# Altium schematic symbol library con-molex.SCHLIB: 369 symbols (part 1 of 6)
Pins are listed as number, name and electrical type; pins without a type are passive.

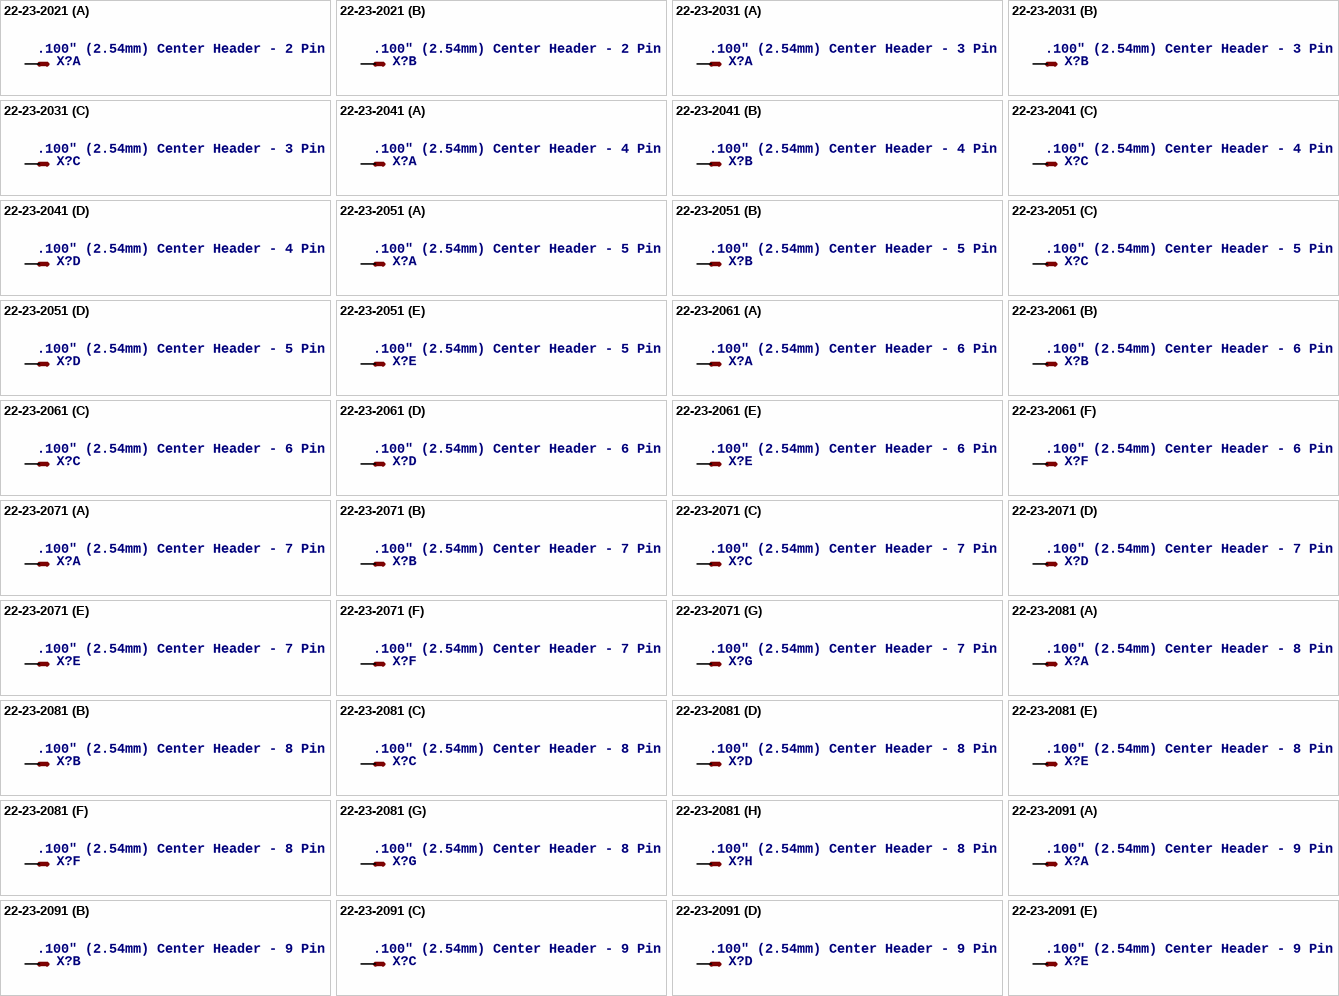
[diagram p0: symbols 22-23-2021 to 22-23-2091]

## 22-23-2021
designator X?, comment .100" (2.54mm) Center Header - 2 Pin
MF: MOLEX
footprint 22-23-2021
part A pins: 1 S
part B pins: 2 S

## 22-23-2031
designator X?, comment .100" (2.54mm) Center Header - 3 Pin
MF: MOLEX
footprint 22-23-2031
part A pins: 1 S
part B pins: 2 S
part C pins: 3 S

## 22-23-2041
designator X?, comment .100" (2.54mm) Center Header - 4 Pin
MF: MOLEX
footprint 22-23-2041
part A pins: 1 S
part B pins: 2 S
part C pins: 3 S
part D pins: 4 S

## 22-23-2051
designator X?, comment .100" (2.54mm) Center Header - 5 Pin
MF: MOLEX
footprint 22-23-2051
part A pins: 1 S
part B pins: 2 S
part C pins: 3 S
part D pins: 4 S
part E pins: 5 S

## 22-23-2061
designator X?, comment .100" (2.54mm) Center Header - 6 Pin
MF: MOLEX
footprint 22-23-2061
part A pins: 1 S
part B pins: 2 S
part C pins: 3 S
part D pins: 4 S
part E pins: 5 S
part F pins: 6 S

## 22-23-2071
designator X?, comment .100" (2.54mm) Center Header - 7 Pin
MF: MOLEX
footprint 22-23-2071
part A pins: 1 S
part B pins: 2 S
part C pins: 3 S
part D pins: 4 S
part E pins: 5 S
part F pins: 6 S
part G pins: 7 S

## 22-23-2081
designator X?, comment .100" (2.54mm) Center Header - 8 Pin
MF: MOLEX
footprint 22-23-2081
part A pins: 1 S
part B pins: 2 S
part C pins: 3 S
part D pins: 4 S
part E pins: 5 S
part F pins: 6 S
part G pins: 7 S
part H pins: 8 S

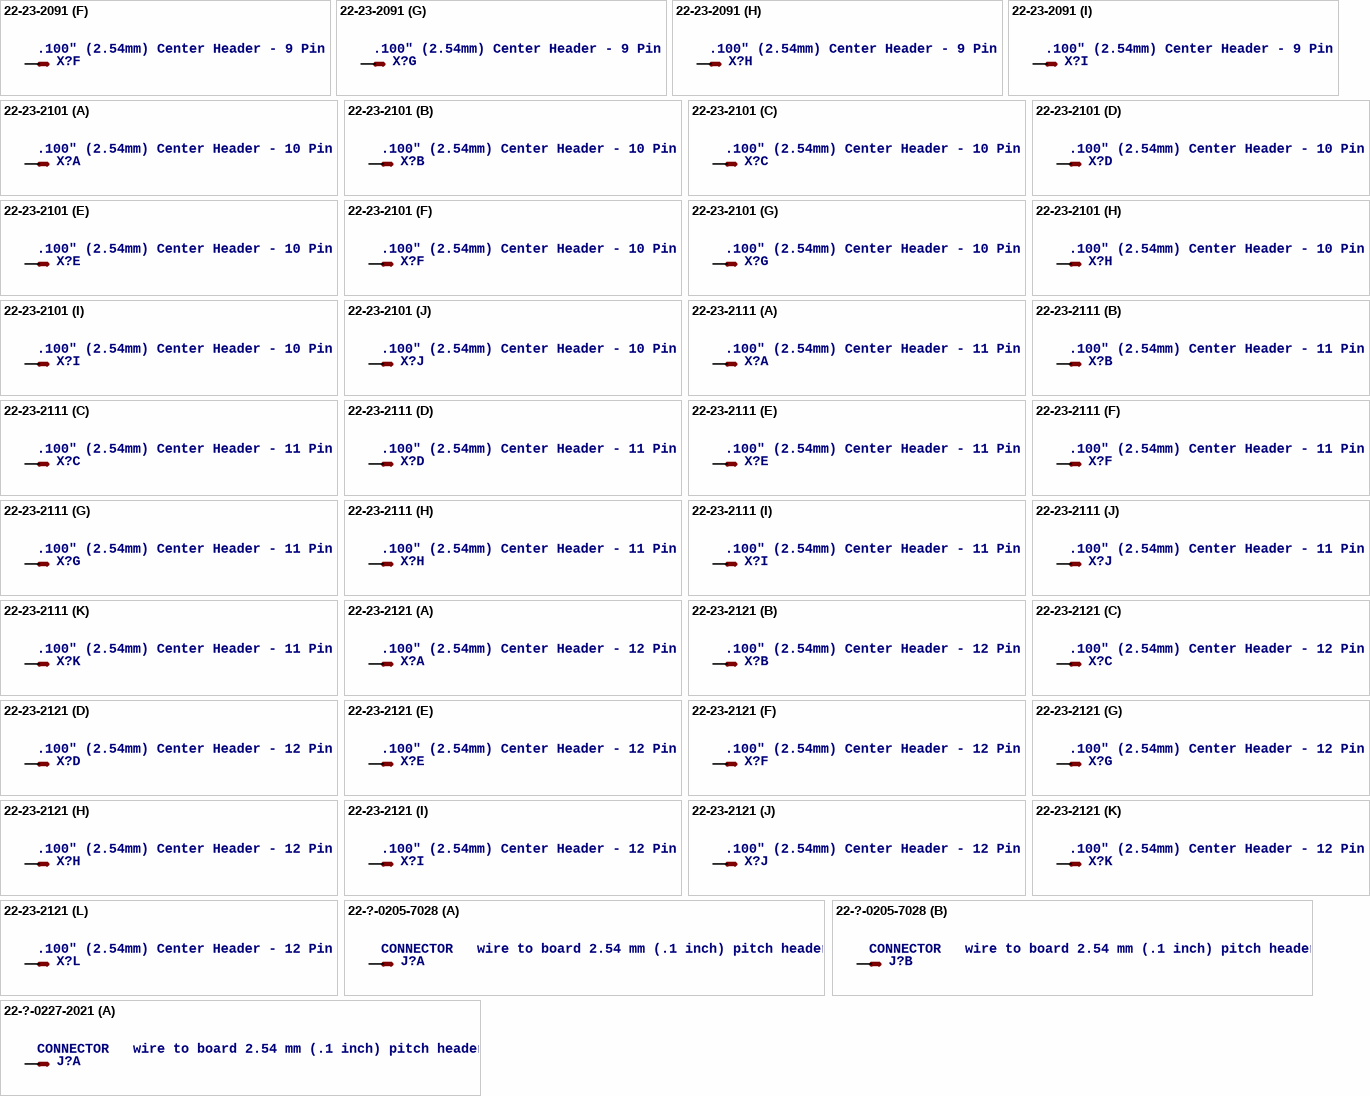
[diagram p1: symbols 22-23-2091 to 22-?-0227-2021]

## 22-23-2091
designator X?, comment .100" (2.54mm) Center Header - 9 Pin
MF: MOLEX
footprint 22-23-2091
part A pins: 1 S
part B pins: 2 S
part C pins: 3 S
part D pins: 4 S
part E pins: 5 S
part F pins: 6 S
part G pins: 7 S
part H pins: 8 S
part I pins: 9 S

## 22-23-2101
designator X?, comment .100" (2.54mm) Center Header - 10 Pin
MF: MOLEX
footprint 22-23-2101
part A pins: 1 S
part B pins: 2 S
part C pins: 3 S
part D pins: 4 S
part E pins: 5 S
part F pins: 6 S
part G pins: 7 S
part H pins: 8 S
part I pins: 9 S
part J pins: 10 S

## 22-23-2111
designator X?, comment .100" (2.54mm) Center Header - 11 Pin
MF: MOLEX
footprint 22-23-2111
part A pins: 1 S
part B pins: 2 S
part C pins: 3 S
part D pins: 4 S
part E pins: 5 S
part F pins: 6 S
part G pins: 7 S
part H pins: 8 S
part I pins: 9 S
part J pins: 10 S
part K pins: 11 S

## 22-23-2121
designator X?, comment .100" (2.54mm) Center Header - 12 Pin
MF: MOLEX
footprint 22-23-2121
part A pins: 1 S
part B pins: 2 S
part C pins: 3 S
part D pins: 4 S
part E pins: 5 S
part F pins: 6 S
part G pins: 7 S
part H pins: 8 S
part I pins: 9 S
part J pins: 10 S
part K pins: 11 S
part L pins: 12 S

## 22-?-0205-7028
designator J?, comment CONNECTOR   wire to board 2.54 mm (.1 inch) pitch header
footprint 7395-02
part A pins: 1 S
part B pins: 2 S

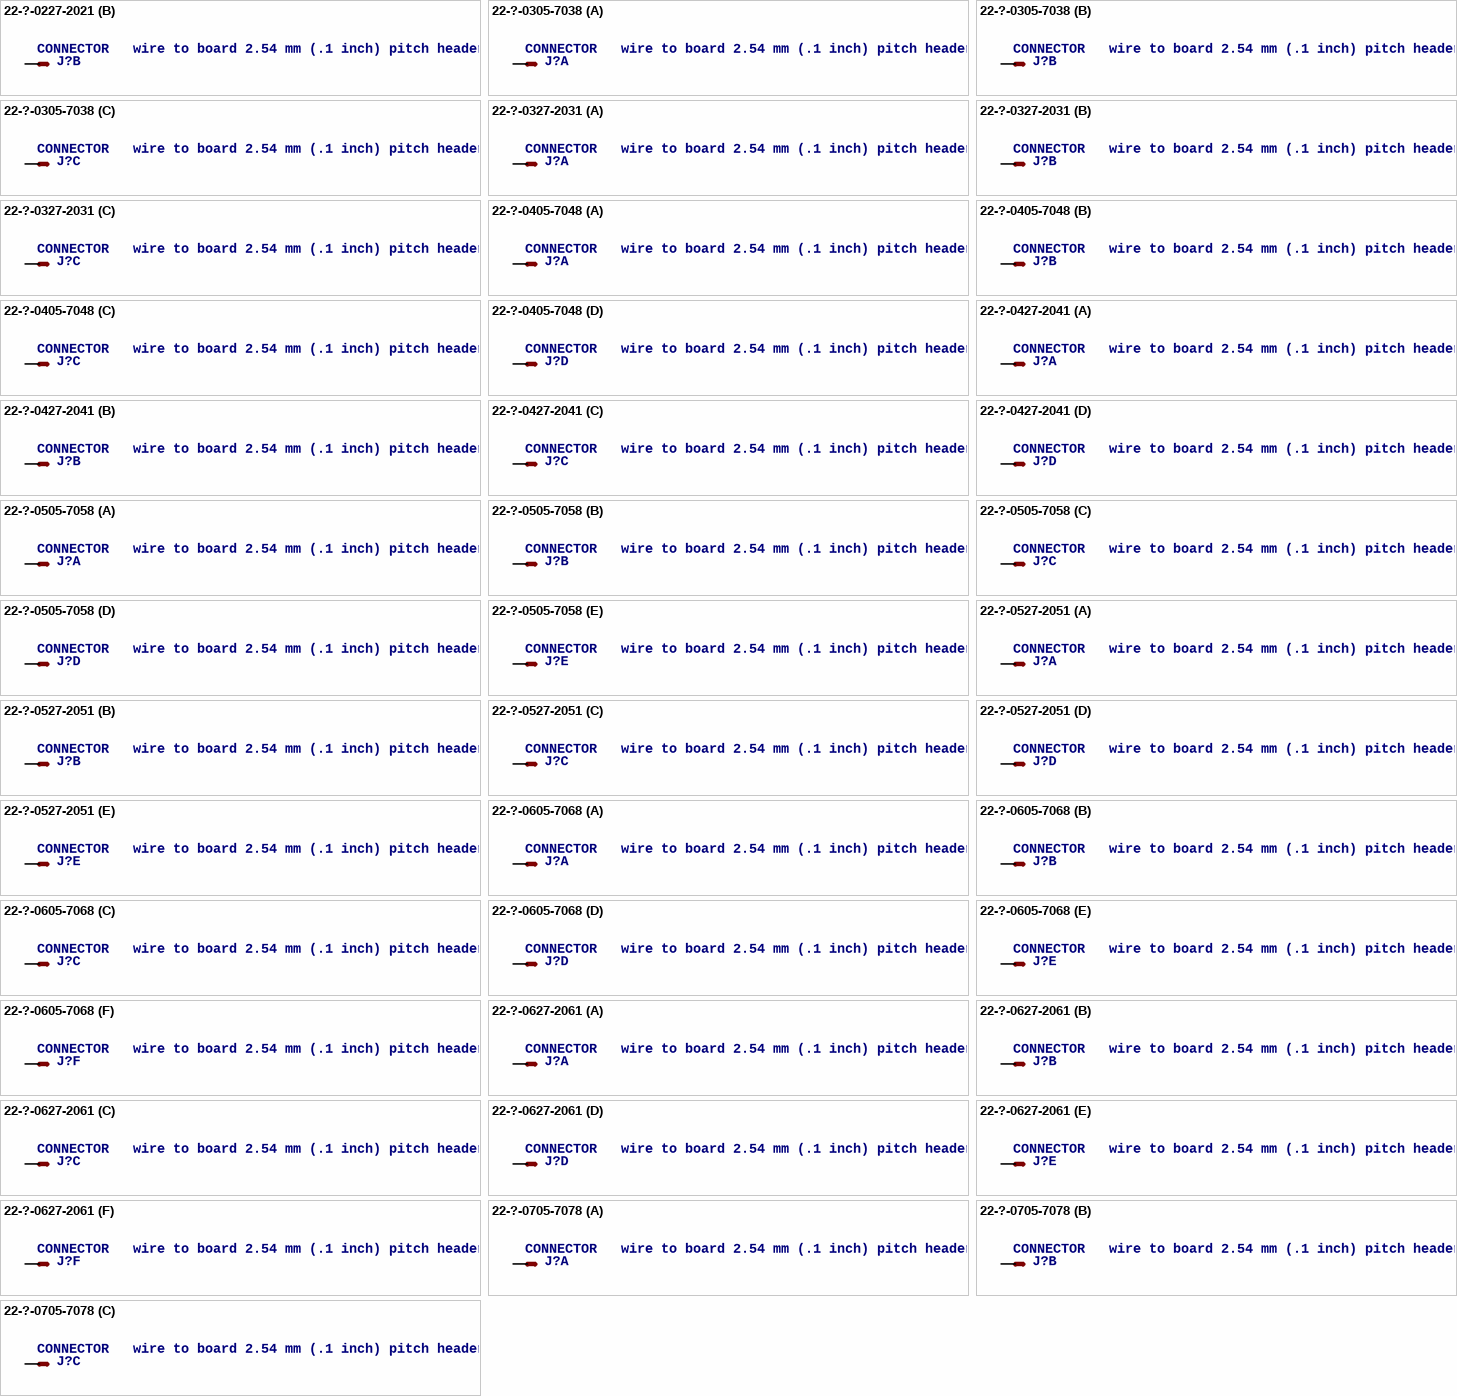
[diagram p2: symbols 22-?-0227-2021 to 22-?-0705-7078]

## 22-?-0227-2021
designator J?, comment CONNECTOR   wire to board 2.54 mm (.1 inch) pitch header
footprint 6410-02
part A pins: 1 S
part B pins: 2 S

## 22-?-0305-7038
designator J?, comment CONNECTOR   wire to board 2.54 mm (.1 inch) pitch header
footprint 7395-03
part A pins: 1 S
part B pins: 2 S
part C pins: 3 S

## 22-?-0327-2031
designator J?, comment CONNECTOR   wire to board 2.54 mm (.1 inch) pitch header
footprint 6410-03
part A pins: 1 S
part B pins: 2 S
part C pins: 3 S

## 22-?-0405-7048
designator J?, comment CONNECTOR   wire to board 2.54 mm (.1 inch) pitch header
footprint 7395-04
part A pins: 1 S
part B pins: 2 S
part C pins: 3 S
part D pins: 4 S

## 22-?-0427-2041
designator J?, comment CONNECTOR   wire to board 2.54 mm (.1 inch) pitch header
footprint 6410-04
part A pins: 1 S
part B pins: 2 S
part C pins: 3 S
part D pins: 4 S

## 22-?-0505-7058
designator J?, comment CONNECTOR   wire to board 2.54 mm (.1 inch) pitch header
footprint 7395-05
part A pins: 1 S
part B pins: 2 S
part C pins: 3 S
part D pins: 4 S
part E pins: 5 S

## 22-?-0527-2051
designator J?, comment CONNECTOR   wire to board 2.54 mm (.1 inch) pitch header
footprint 6410-05
part A pins: 1 S
part B pins: 2 S
part C pins: 3 S
part D pins: 4 S
part E pins: 5 S

## 22-?-0605-7068
designator J?, comment CONNECTOR   wire to board 2.54 mm (.1 inch) pitch header
footprint 7395-06
part A pins: 1 S
part B pins: 2 S
part C pins: 3 S
part D pins: 4 S
part E pins: 5 S
part F pins: 6 S

## 22-?-0627-2061
designator J?, comment CONNECTOR   wire to board 2.54 mm (.1 inch) pitch header
footprint 6410-06
part A pins: 1 S
part B pins: 2 S
part C pins: 3 S
part D pins: 4 S
part E pins: 5 S
part F pins: 6 S

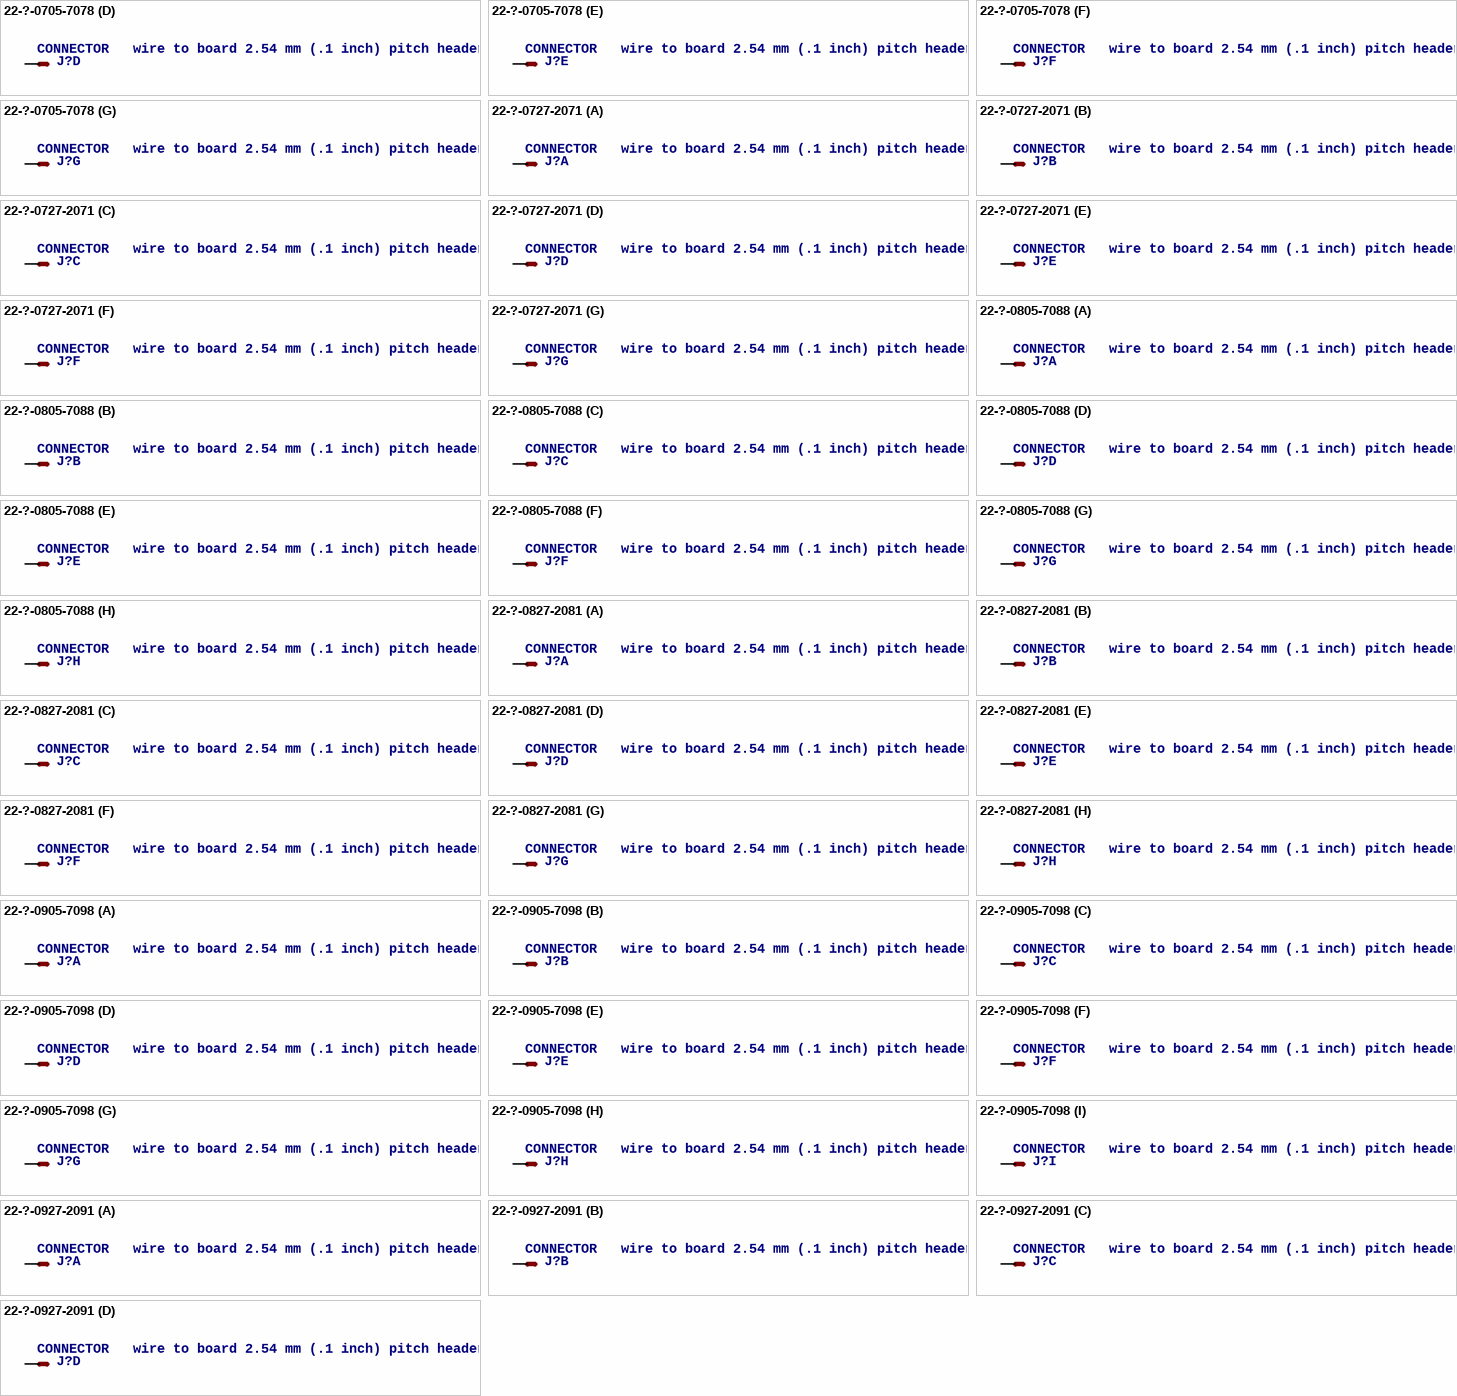
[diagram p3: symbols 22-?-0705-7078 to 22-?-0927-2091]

## 22-?-0705-7078
designator J?, comment CONNECTOR   wire to board 2.54 mm (.1 inch) pitch header
footprint 7395-07
part A pins: 1 S
part B pins: 2 S
part C pins: 3 S
part D pins: 4 S
part E pins: 5 S
part F pins: 6 S
part G pins: 7 S

## 22-?-0727-2071
designator J?, comment CONNECTOR   wire to board 2.54 mm (.1 inch) pitch header
footprint 6410-07
part A pins: 1 S
part B pins: 2 S
part C pins: 3 S
part D pins: 4 S
part E pins: 5 S
part F pins: 6 S
part G pins: 7 S

## 22-?-0805-7088
designator J?, comment CONNECTOR   wire to board 2.54 mm (.1 inch) pitch header
footprint 7395-08
part A pins: 1 S
part B pins: 2 S
part C pins: 3 S
part D pins: 4 S
part E pins: 5 S
part F pins: 6 S
part G pins: 7 S
part H pins: 8 S

## 22-?-0827-2081
designator J?, comment CONNECTOR   wire to board 2.54 mm (.1 inch) pitch header
footprint 6410-08
part A pins: 1 S
part B pins: 2 S
part C pins: 3 S
part D pins: 4 S
part E pins: 5 S
part F pins: 6 S
part G pins: 7 S
part H pins: 8 S

## 22-?-0905-7098
designator J?, comment CONNECTOR   wire to board 2.54 mm (.1 inch) pitch header
footprint 7395-09
part A pins: 1 S
part B pins: 2 S
part C pins: 3 S
part D pins: 4 S
part E pins: 5 S
part F pins: 6 S
part G pins: 7 S
part H pins: 8 S
part I pins: 9 S

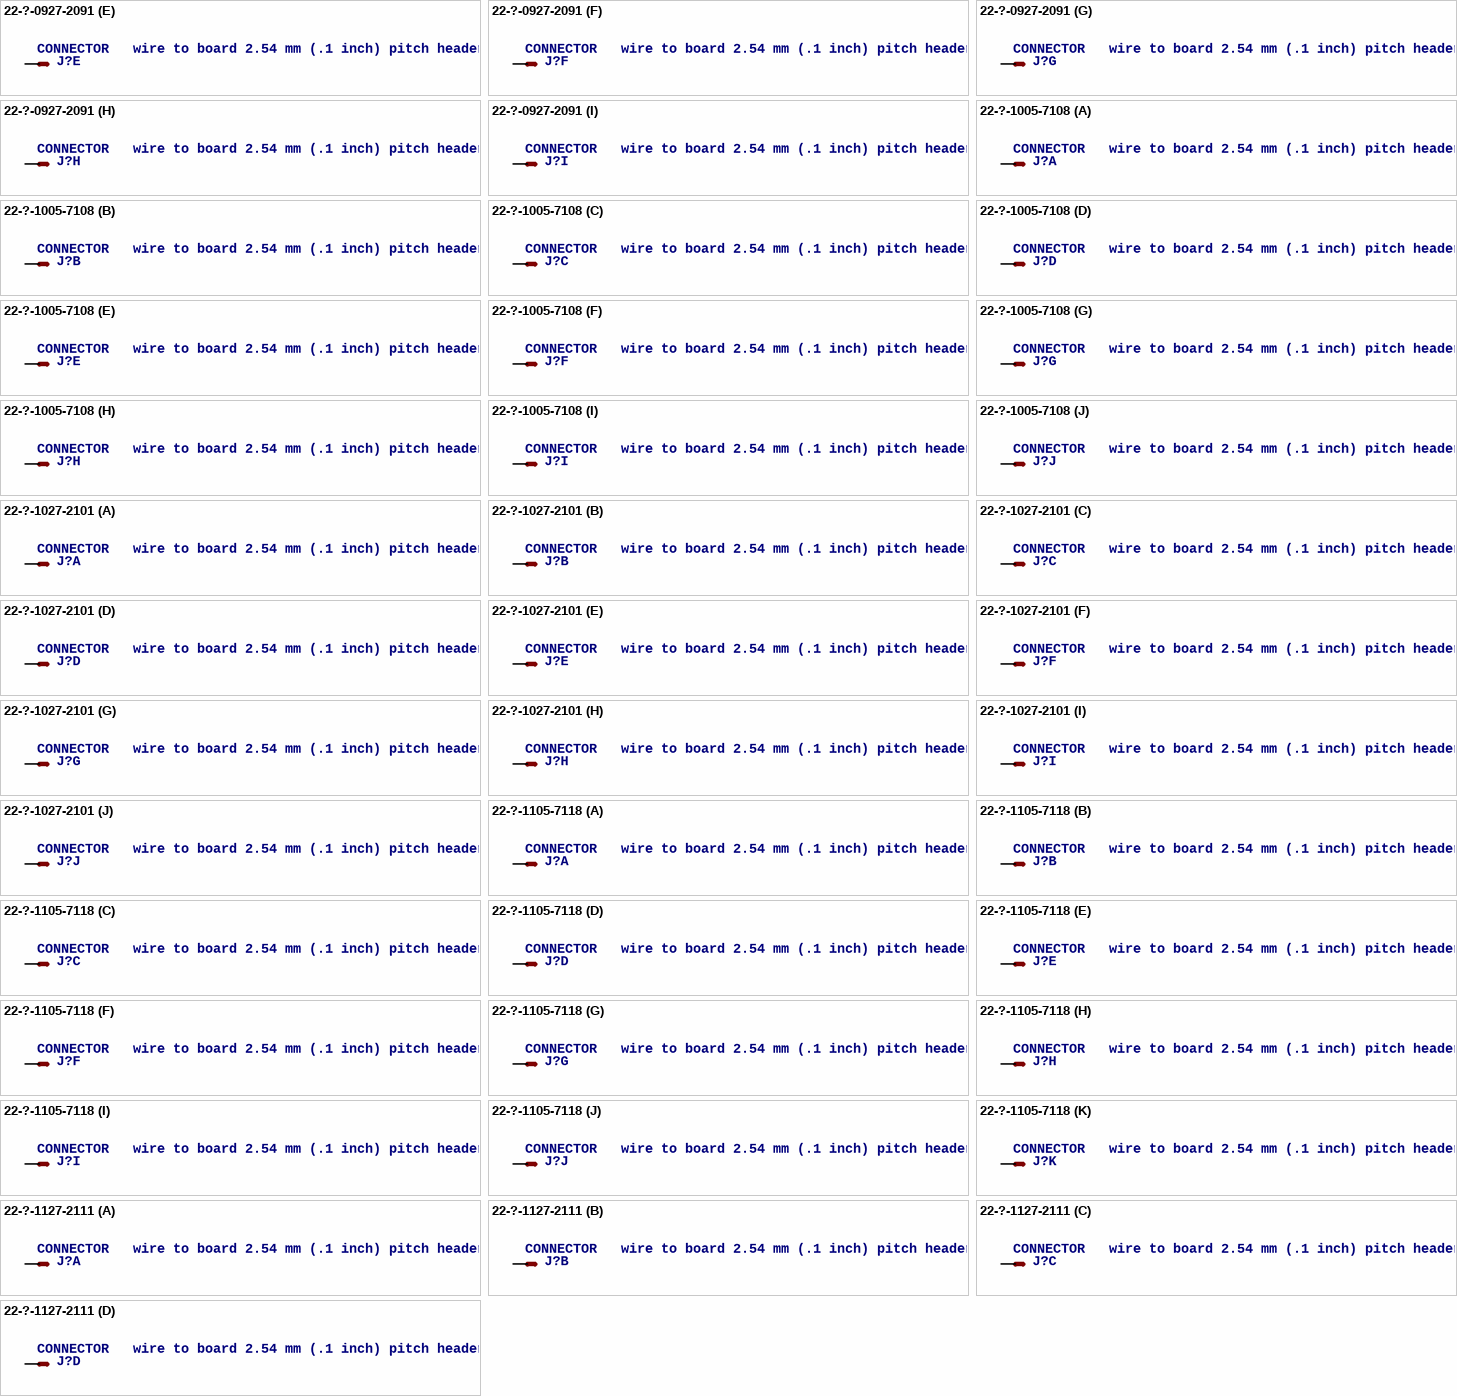
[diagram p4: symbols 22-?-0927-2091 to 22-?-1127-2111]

## 22-?-0927-2091
designator J?, comment CONNECTOR   wire to board 2.54 mm (.1 inch) pitch header
footprint 6410-09
part A pins: 1 S
part B pins: 2 S
part C pins: 3 S
part D pins: 4 S
part E pins: 5 S
part F pins: 6 S
part G pins: 7 S
part H pins: 8 S
part I pins: 9 S

## 22-?-1005-7108
designator J?, comment CONNECTOR   wire to board 2.54 mm (.1 inch) pitch header
footprint 7395-10
part A pins: 1 S
part B pins: 2 S
part C pins: 3 S
part D pins: 4 S
part E pins: 5 S
part F pins: 6 S
part G pins: 7 S
part H pins: 8 S
part I pins: 9 S
part J pins: 10 S

## 22-?-1027-2101
designator J?, comment CONNECTOR   wire to board 2.54 mm (.1 inch) pitch header
footprint 6410-10
part A pins: 1 S
part B pins: 2 S
part C pins: 3 S
part D pins: 4 S
part E pins: 5 S
part F pins: 6 S
part G pins: 7 S
part H pins: 8 S
part I pins: 9 S
part J pins: 10 S

## 22-?-1105-7118
designator J?, comment CONNECTOR   wire to board 2.54 mm (.1 inch) pitch header
footprint 7395-11
part A pins: 1 S
part B pins: 2 S
part C pins: 3 S
part D pins: 4 S
part E pins: 5 S
part F pins: 6 S
part G pins: 7 S
part H pins: 8 S
part I pins: 9 S
part J pins: 10 S
part K pins: 11 S

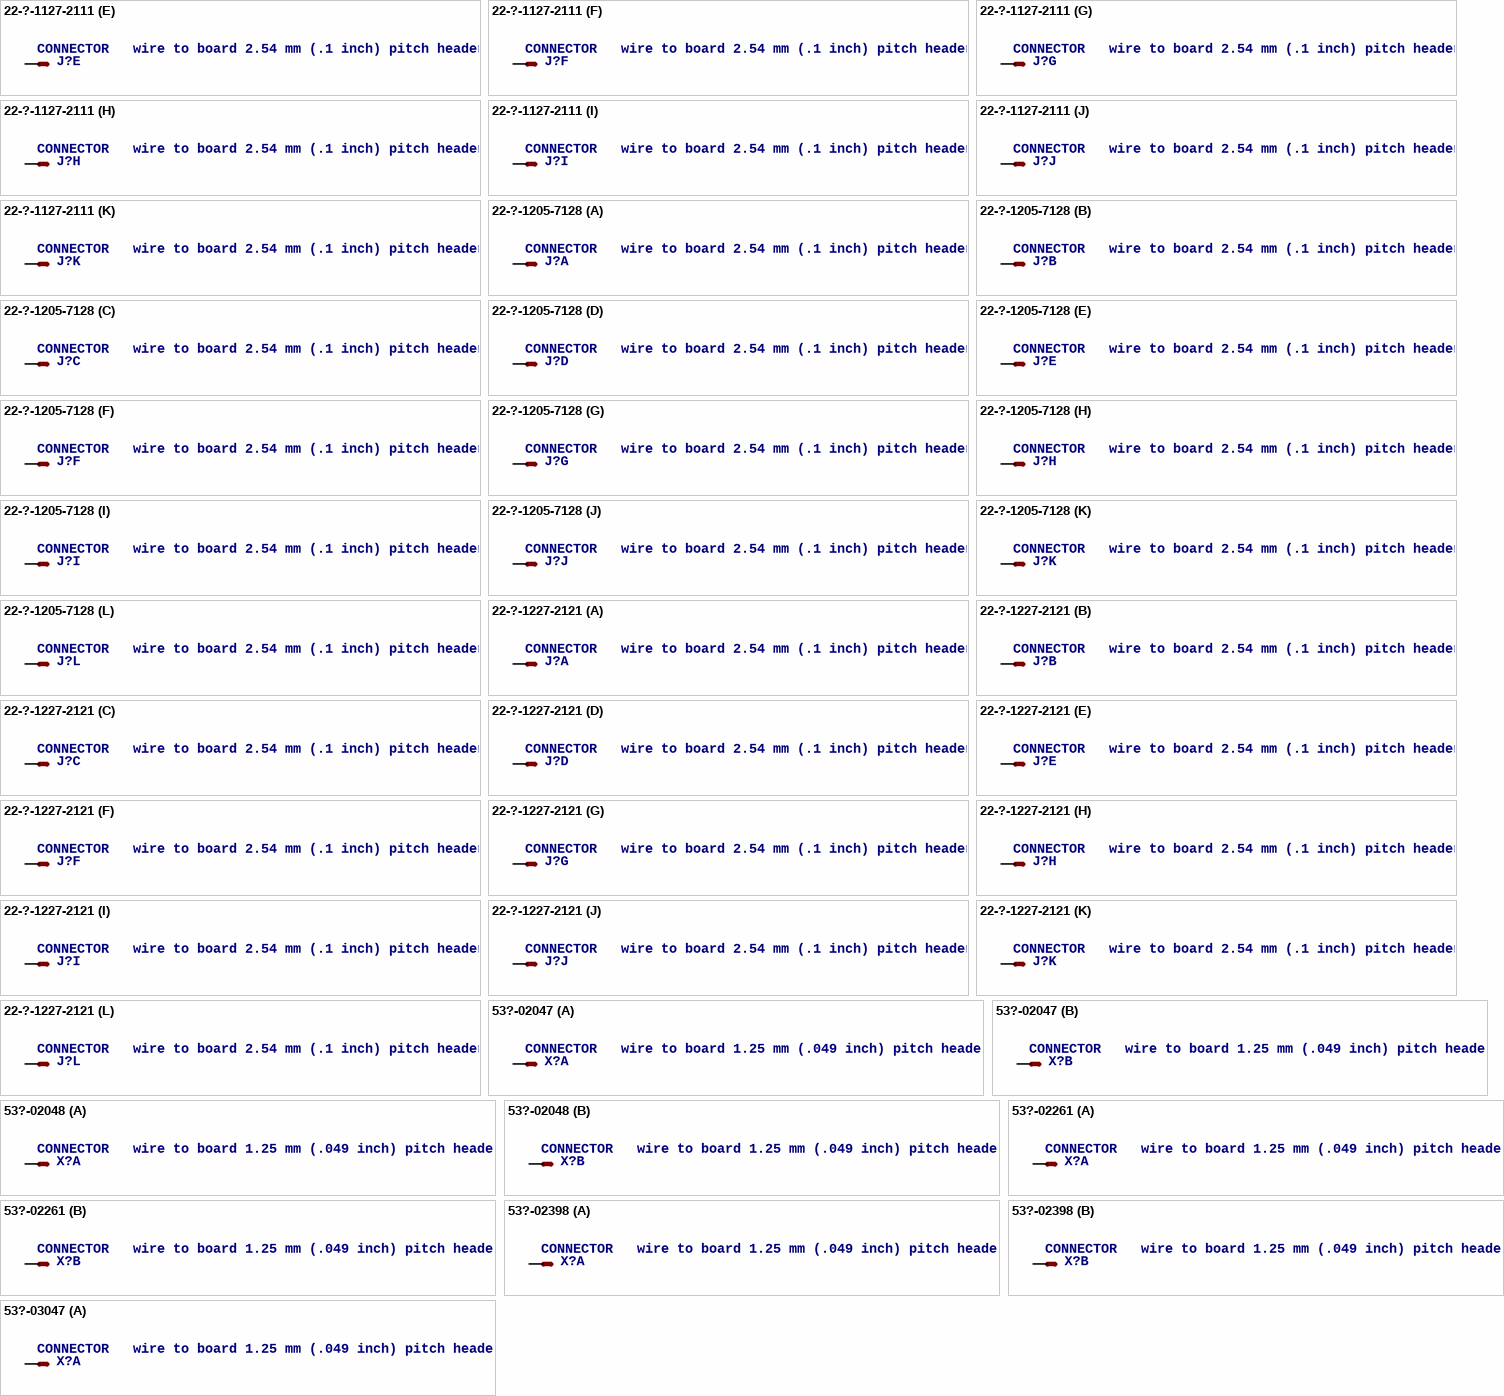
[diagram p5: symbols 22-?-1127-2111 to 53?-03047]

## 22-?-1127-2111
designator J?, comment CONNECTOR   wire to board 2.54 mm (.1 inch) pitch header
footprint 6410-11
part A pins: 1 S
part B pins: 2 S
part C pins: 3 S
part D pins: 4 S
part E pins: 5 S
part F pins: 6 S
part G pins: 7 S
part H pins: 8 S
part I pins: 9 S
part J pins: 10 S
part K pins: 11 S

## 22-?-1205-7128
designator J?, comment CONNECTOR   wire to board 2.54 mm (.1 inch) pitch header
footprint 7395-12
part A pins: 1 S
part B pins: 2 S
part C pins: 3 S
part D pins: 4 S
part E pins: 5 S
part F pins: 6 S
part G pins: 7 S
part H pins: 8 S
part I pins: 9 S
part J pins: 10 S
part K pins: 11 S
part L pins: 12 S

## 22-?-1227-2121
designator J?, comment CONNECTOR   wire to board 2.54 mm (.1 inch) pitch header
footprint 6410-12
part A pins: 1 S
part B pins: 2 S
part C pins: 3 S
part D pins: 4 S
part E pins: 5 S
part F pins: 6 S
part G pins: 7 S
part H pins: 8 S
part I pins: 9 S
part J pins: 10 S
part K pins: 11 S
part L pins: 12 S

## 53?-02047
designator X?, comment CONNECTOR   wire to board 1.25 mm (.049 inch) pitch header
MPN: 53047-0210; MF: MOLEX
footprint 53047-02
part A pins: 1 S
part B pins: 2 S

## 53?-02048
designator X?, comment CONNECTOR   wire to board 1.25 mm (.049 inch) pitch header
MPN: 53048-0210; MF: MOLEX
footprint 53048-02
part A pins: 1 S
part B pins: 2 S

## 53?-02261
designator X?, comment CONNECTOR   wire to board 1.25 mm (.049 inch) pitch header
footprint 53261-02
part A pins: 1 S
part B pins: 2 S

## 53?-02398
designator X?, comment CONNECTOR   wire to board 1.25 mm (.049 inch) pitch header
footprint 53398-02
part A pins: 1 S
part B pins: 2 S

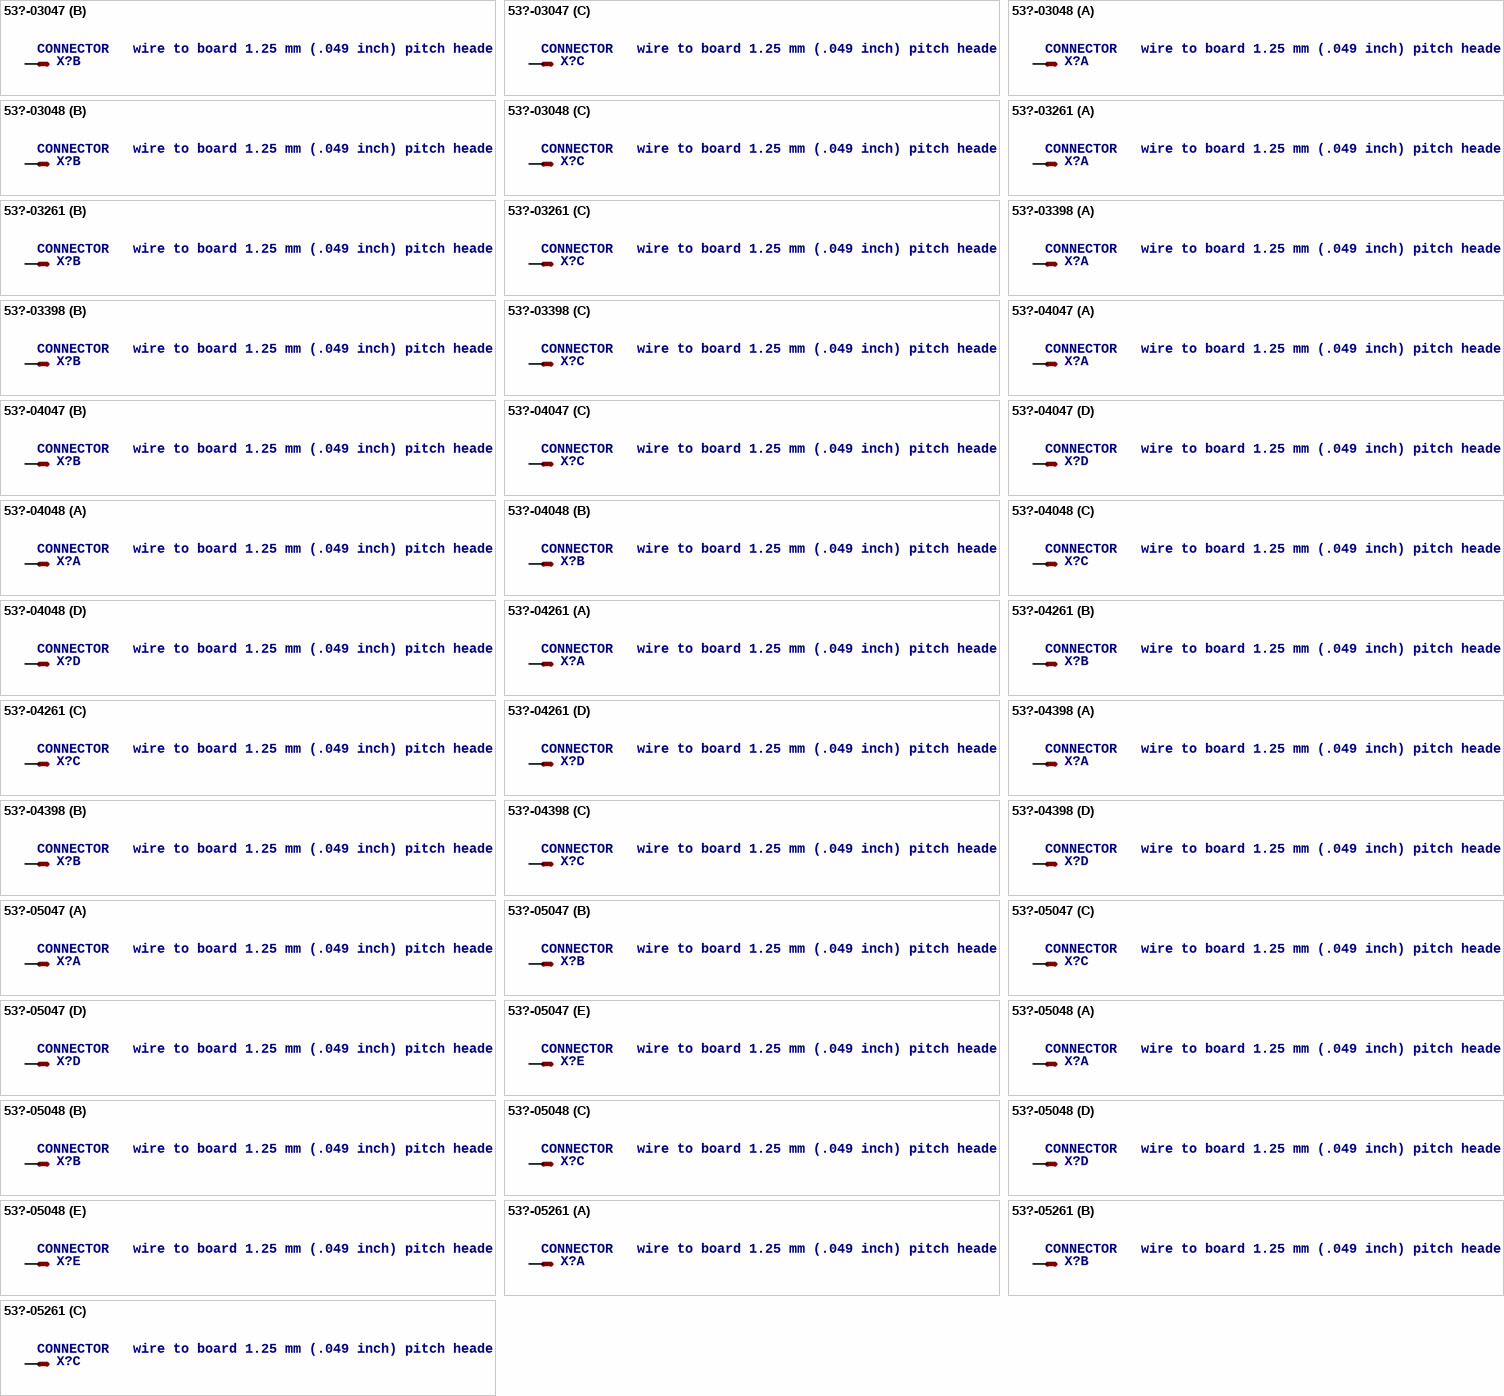
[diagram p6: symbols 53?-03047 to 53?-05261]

## 53?-03047
designator X?, comment CONNECTOR   wire to board 1.25 mm (.049 inch) pitch header
MPN: 530470310
footprint 53047-03
part A pins: 1 S
part B pins: 2 S
part C pins: 3 S

## 53?-03048
designator X?, comment CONNECTOR   wire to board 1.25 mm (.049 inch) pitch header
MPN: 53048-0310; MF: WALDOM/MOLEX
footprint 53048-03
part A pins: 1 S
part B pins: 2 S
part C pins: 3 S

## 53?-03261
designator X?, comment CONNECTOR   wire to board 1.25 mm (.049 inch) pitch header
MPN: 53261-0390; MF: MOLEX
footprint 53261-03
part A pins: 1 S
part B pins: 2 S
part C pins: 3 S

## 53?-03398
designator X?, comment CONNECTOR   wire to board 1.25 mm (.049 inch) pitch header
footprint 53398-03
part A pins: 1 S
part B pins: 2 S
part C pins: 3 S

## 53?-04047
designator X?, comment CONNECTOR   wire to board 1.25 mm (.049 inch) pitch header
MPN: 53047-0410; MF: WALDOM/MOLEX
footprint 53047-04
part A pins: 1 S
part B pins: 2 S
part C pins: 3 S
part D pins: 4 S

## 53?-04048
designator X?, comment CONNECTOR   wire to board 1.25 mm (.049 inch) pitch header
MPN: 53048-0410; MF: MOLEX
footprint 53048-04
part A pins: 1 S
part B pins: 2 S
part C pins: 3 S
part D pins: 4 S

## 53?-04261
designator X?, comment CONNECTOR   wire to board 1.25 mm (.049 inch) pitch header
footprint 53261-04
part A pins: 1 S
part B pins: 2 S
part C pins: 3 S
part D pins: 4 S

## 53?-04398
designator X?, comment CONNECTOR   wire to board 1.25 mm (.049 inch) pitch header
footprint 53398-04
part A pins: 1 S
part B pins: 2 S
part C pins: 3 S
part D pins: 4 S

## 53?-05047
designator X?, comment CONNECTOR   wire to board 1.25 mm (.049 inch) pitch header
MPN: 53047-0510; MF: MOLEX
footprint 53047-05
part A pins: 1 S
part B pins: 2 S
part C pins: 3 S
part D pins: 4 S
part E pins: 5 S

## 53?-05048
designator X?, comment CONNECTOR   wire to board 1.25 mm (.049 inch) pitch header
MPN: 53048-0510; MF: MOLEX
footprint 53048-05
part A pins: 1 S
part B pins: 2 S
part C pins: 3 S
part D pins: 4 S
part E pins: 5 S

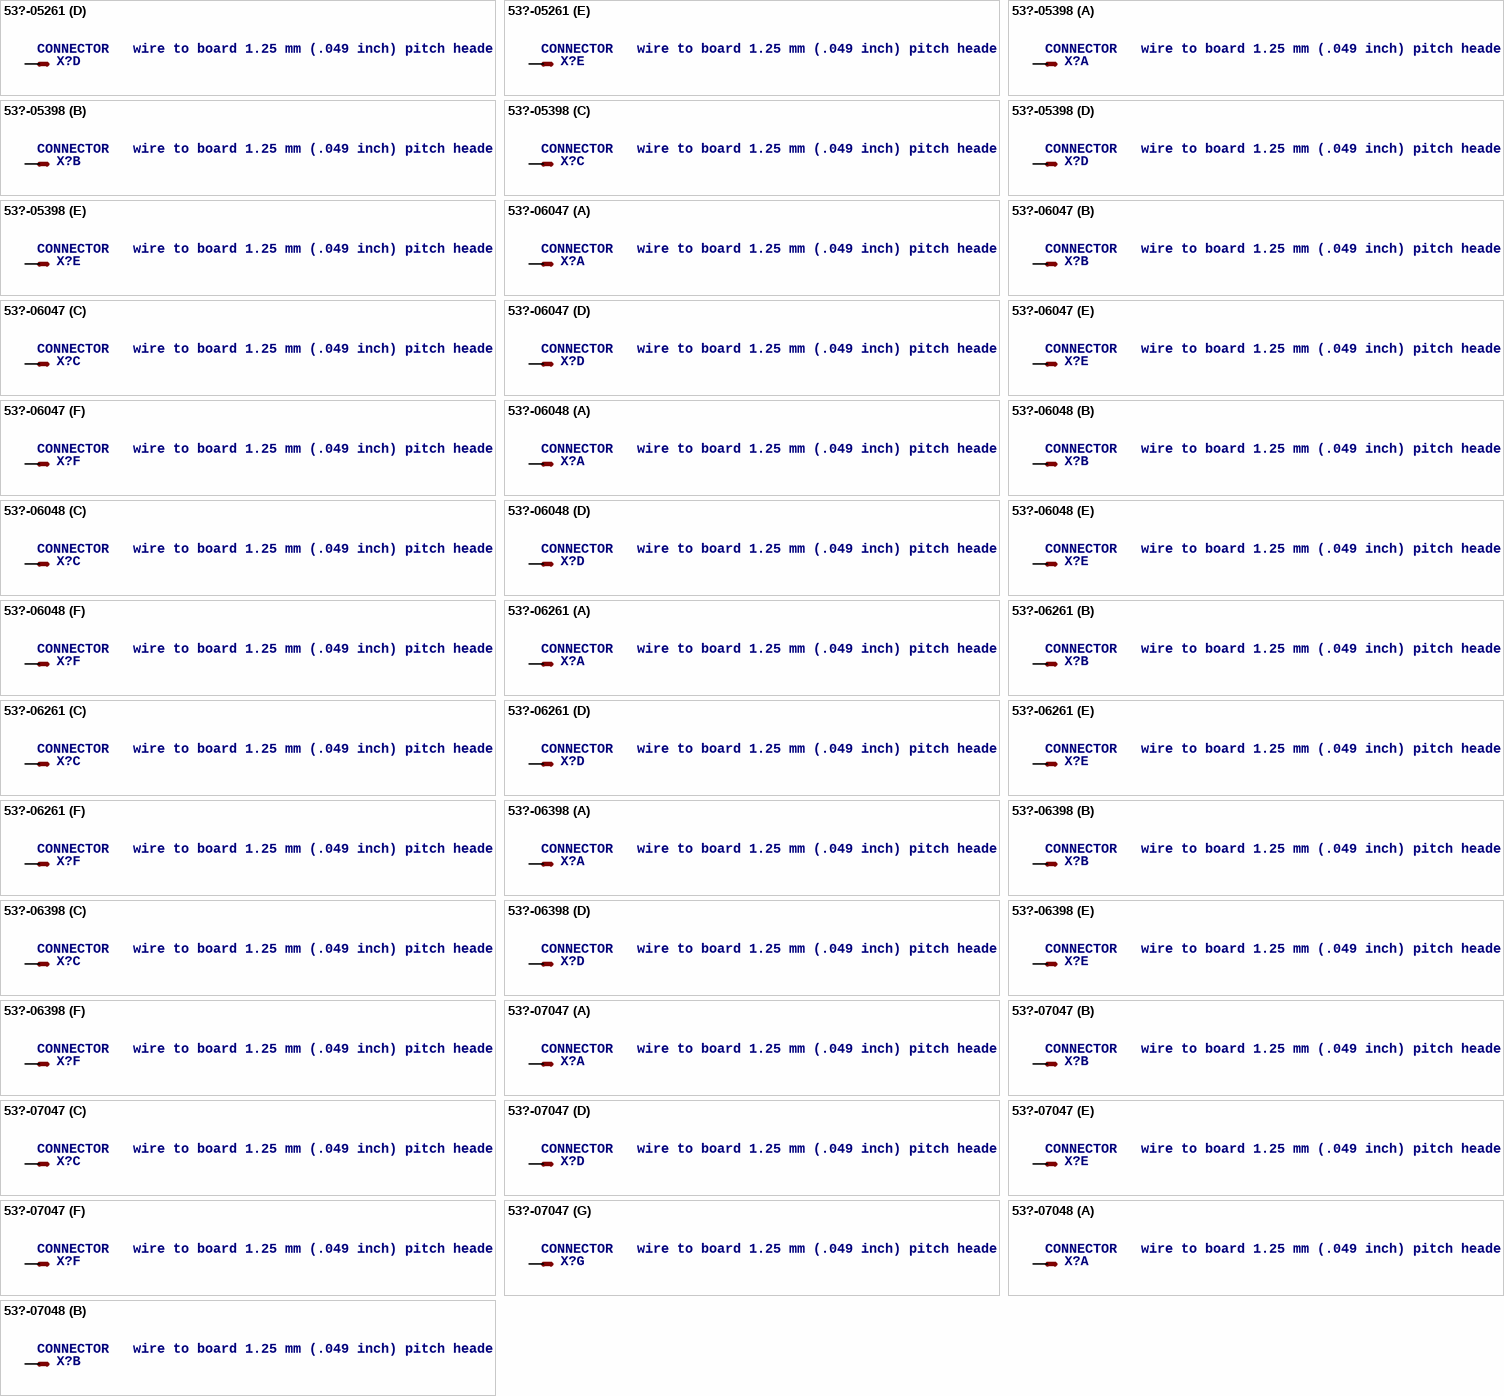
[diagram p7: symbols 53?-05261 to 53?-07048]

## 53?-05261
designator X?, comment CONNECTOR   wire to board 1.25 mm (.049 inch) pitch header
footprint 53261-05
part A pins: 1 S
part B pins: 2 S
part C pins: 3 S
part D pins: 4 S
part E pins: 5 S

## 53?-05398
designator X?, comment CONNECTOR   wire to board 1.25 mm (.049 inch) pitch header
footprint 53398-05
part A pins: 1 S
part B pins: 2 S
part C pins: 3 S
part D pins: 4 S
part E pins: 5 S

## 53?-06047
designator X?, comment CONNECTOR   wire to board 1.25 mm (.049 inch) pitch header
MPN: 53047-0610-C
footprint 53047-06
part A pins: 1 S
part B pins: 2 S
part C pins: 3 S
part D pins: 4 S
part E pins: 5 S
part F pins: 6 S

## 53?-06048
designator X?, comment CONNECTOR   wire to board 1.25 mm (.049 inch) pitch header
MPN: 53048-0610; MF: WALDOM/MOLEX
footprint 53048-06
part A pins: 1 S
part B pins: 2 S
part C pins: 3 S
part D pins: 4 S
part E pins: 5 S
part F pins: 6 S

## 53?-06261
designator X?, comment CONNECTOR   wire to board 1.25 mm (.049 inch) pitch header
footprint 53261-06
part A pins: 1 S
part B pins: 2 S
part C pins: 3 S
part D pins: 4 S
part E pins: 5 S
part F pins: 6 S

## 53?-06398
designator X?, comment CONNECTOR   wire to board 1.25 mm (.049 inch) pitch header
footprint 53398-06
part A pins: 1 S
part B pins: 2 S
part C pins: 3 S
part D pins: 4 S
part E pins: 5 S
part F pins: 6 S

## 53?-07047
designator X?, comment CONNECTOR   wire to board 1.25 mm (.049 inch) pitch header
MPN: 53047-0710-C
footprint 53047-07
part A pins: 1 S
part B pins: 2 S
part C pins: 3 S
part D pins: 4 S
part E pins: 5 S
part F pins: 6 S
part G pins: 7 S

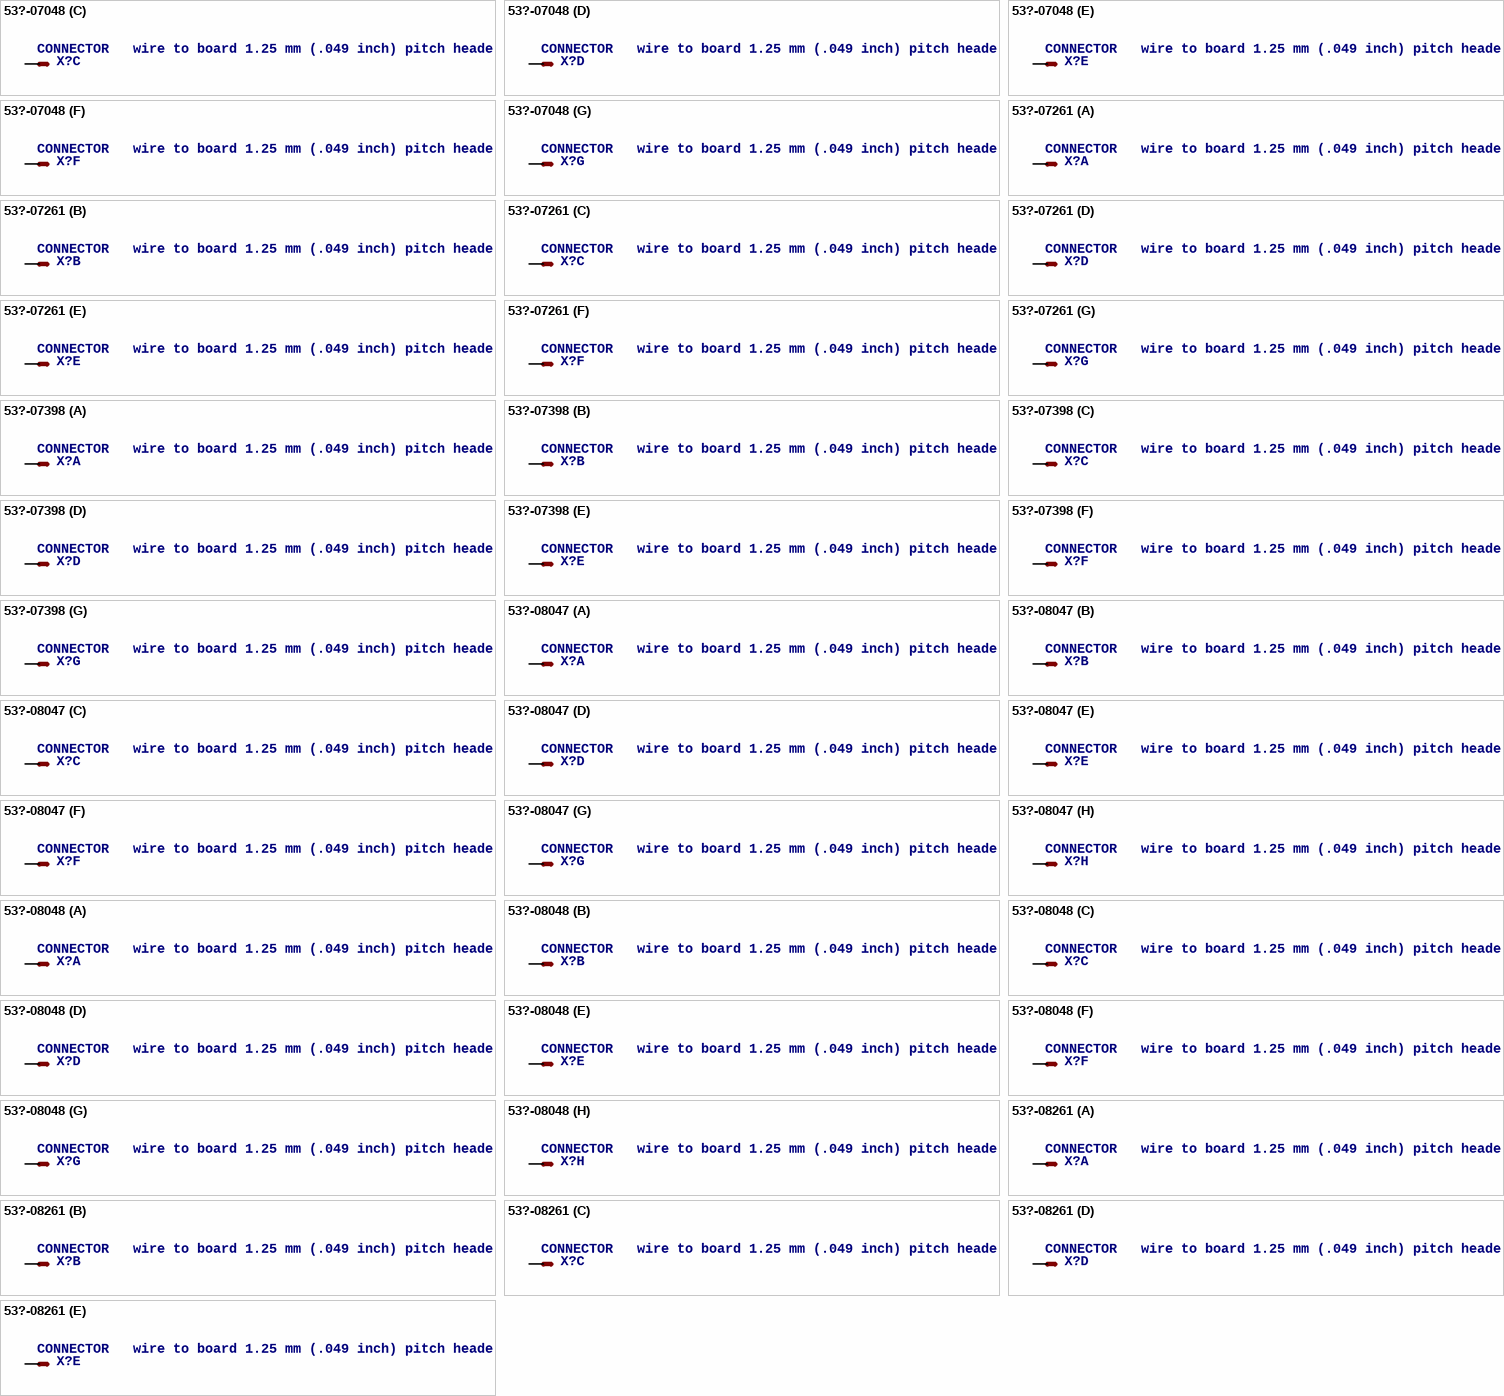
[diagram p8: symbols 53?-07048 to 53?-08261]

## 53?-07048
designator X?, comment CONNECTOR   wire to board 1.25 mm (.049 inch) pitch header
MPN: 53048-0710
footprint 53048-07
part A pins: 1 S
part B pins: 2 S
part C pins: 3 S
part D pins: 4 S
part E pins: 5 S
part F pins: 6 S
part G pins: 7 S

## 53?-07261
designator X?, comment CONNECTOR   wire to board 1.25 mm (.049 inch) pitch header
footprint 53261-07
part A pins: 1 S
part B pins: 2 S
part C pins: 3 S
part D pins: 4 S
part E pins: 5 S
part F pins: 6 S
part G pins: 7 S

## 53?-07398
designator X?, comment CONNECTOR   wire to board 1.25 mm (.049 inch) pitch header
footprint 53398-07
part A pins: 1 S
part B pins: 2 S
part C pins: 3 S
part D pins: 4 S
part E pins: 5 S
part F pins: 6 S
part G pins: 7 S

## 53?-08047
designator X?, comment CONNECTOR   wire to board 1.25 mm (.049 inch) pitch header
MPN: 53047-0810
footprint 53047-08
part A pins: 1 S
part B pins: 2 S
part C pins: 3 S
part D pins: 4 S
part E pins: 5 S
part F pins: 6 S
part G pins: 7 S
part H pins: 8 S

## 53?-08048
designator X?, comment CONNECTOR   wire to board 1.25 mm (.049 inch) pitch header
MPN: 53048-0810; MF: WALDOM/MOLEX
footprint 53048-08
part A pins: 1 S
part B pins: 2 S
part C pins: 3 S
part D pins: 4 S
part E pins: 5 S
part F pins: 6 S
part G pins: 7 S
part H pins: 8 S

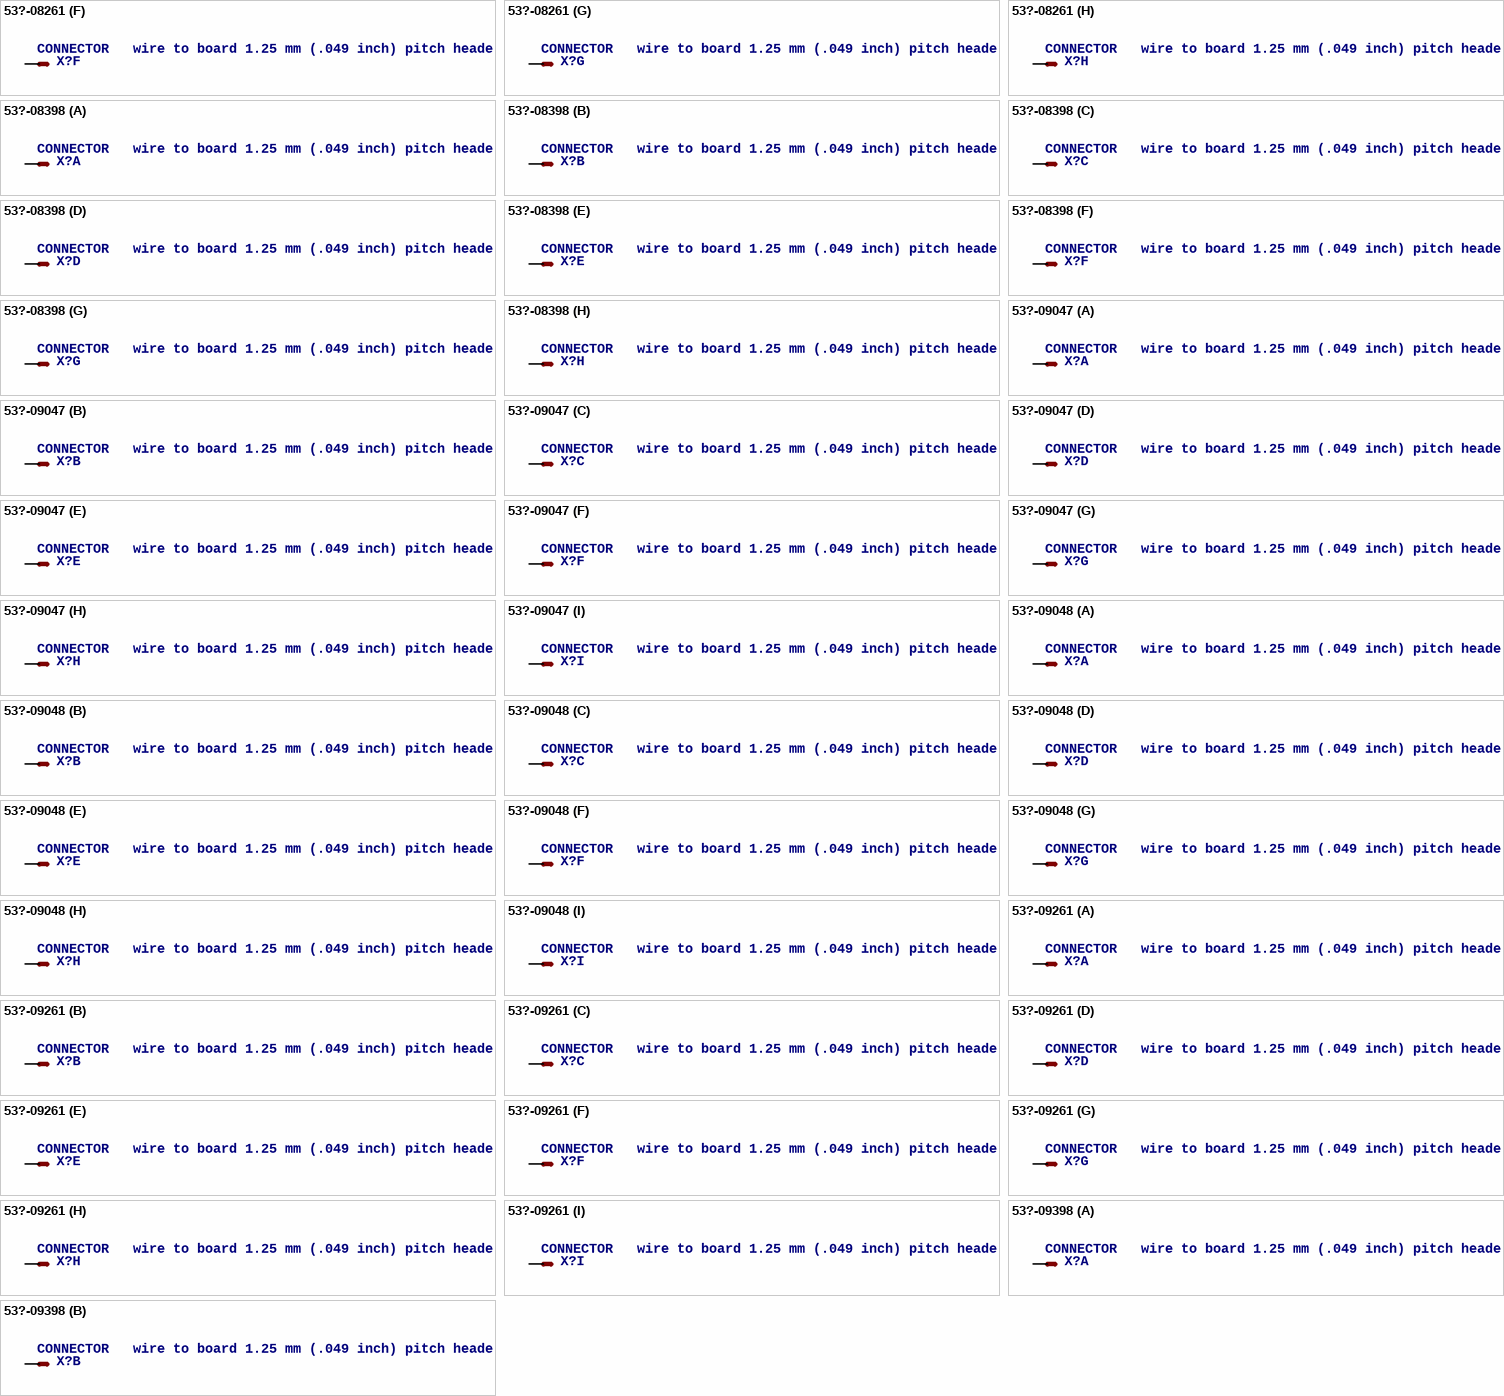
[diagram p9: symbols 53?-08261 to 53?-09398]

## 53?-08261
designator X?, comment CONNECTOR   wire to board 1.25 mm (.049 inch) pitch header
footprint 53261-08
part A pins: 1 S
part B pins: 2 S
part C pins: 3 S
part D pins: 4 S
part E pins: 5 S
part F pins: 6 S
part G pins: 7 S
part H pins: 8 S

## 53?-08398
designator X?, comment CONNECTOR   wire to board 1.25 mm (.049 inch) pitch header
footprint 53398-08
part A pins: 1 S
part B pins: 2 S
part C pins: 3 S
part D pins: 4 S
part E pins: 5 S
part F pins: 6 S
part G pins: 7 S
part H pins: 8 S

## 53?-09047
designator X?, comment CONNECTOR   wire to board 1.25 mm (.049 inch) pitch header
MPN: 53047-0910
footprint 53047-09
part A pins: 1 S
part B pins: 2 S
part C pins: 3 S
part D pins: 4 S
part E pins: 5 S
part F pins: 6 S
part G pins: 7 S
part H pins: 8 S
part I pins: 9 S

## 53?-09048
designator X?, comment CONNECTOR   wire to board 1.25 mm (.049 inch) pitch header
MPN: 53048-0910
footprint 53048-09
part A pins: 1 S
part B pins: 2 S
part C pins: 3 S
part D pins: 4 S
part E pins: 5 S
part F pins: 6 S
part G pins: 7 S
part H pins: 8 S
part I pins: 9 S

## 53?-09261
designator X?, comment CONNECTOR   wire to board 1.25 mm (.049 inch) pitch header
MPN: 53261-0971
footprint 53261-09
part A pins: 1 S
part B pins: 2 S
part C pins: 3 S
part D pins: 4 S
part E pins: 5 S
part F pins: 6 S
part G pins: 7 S
part H pins: 8 S
part I pins: 9 S

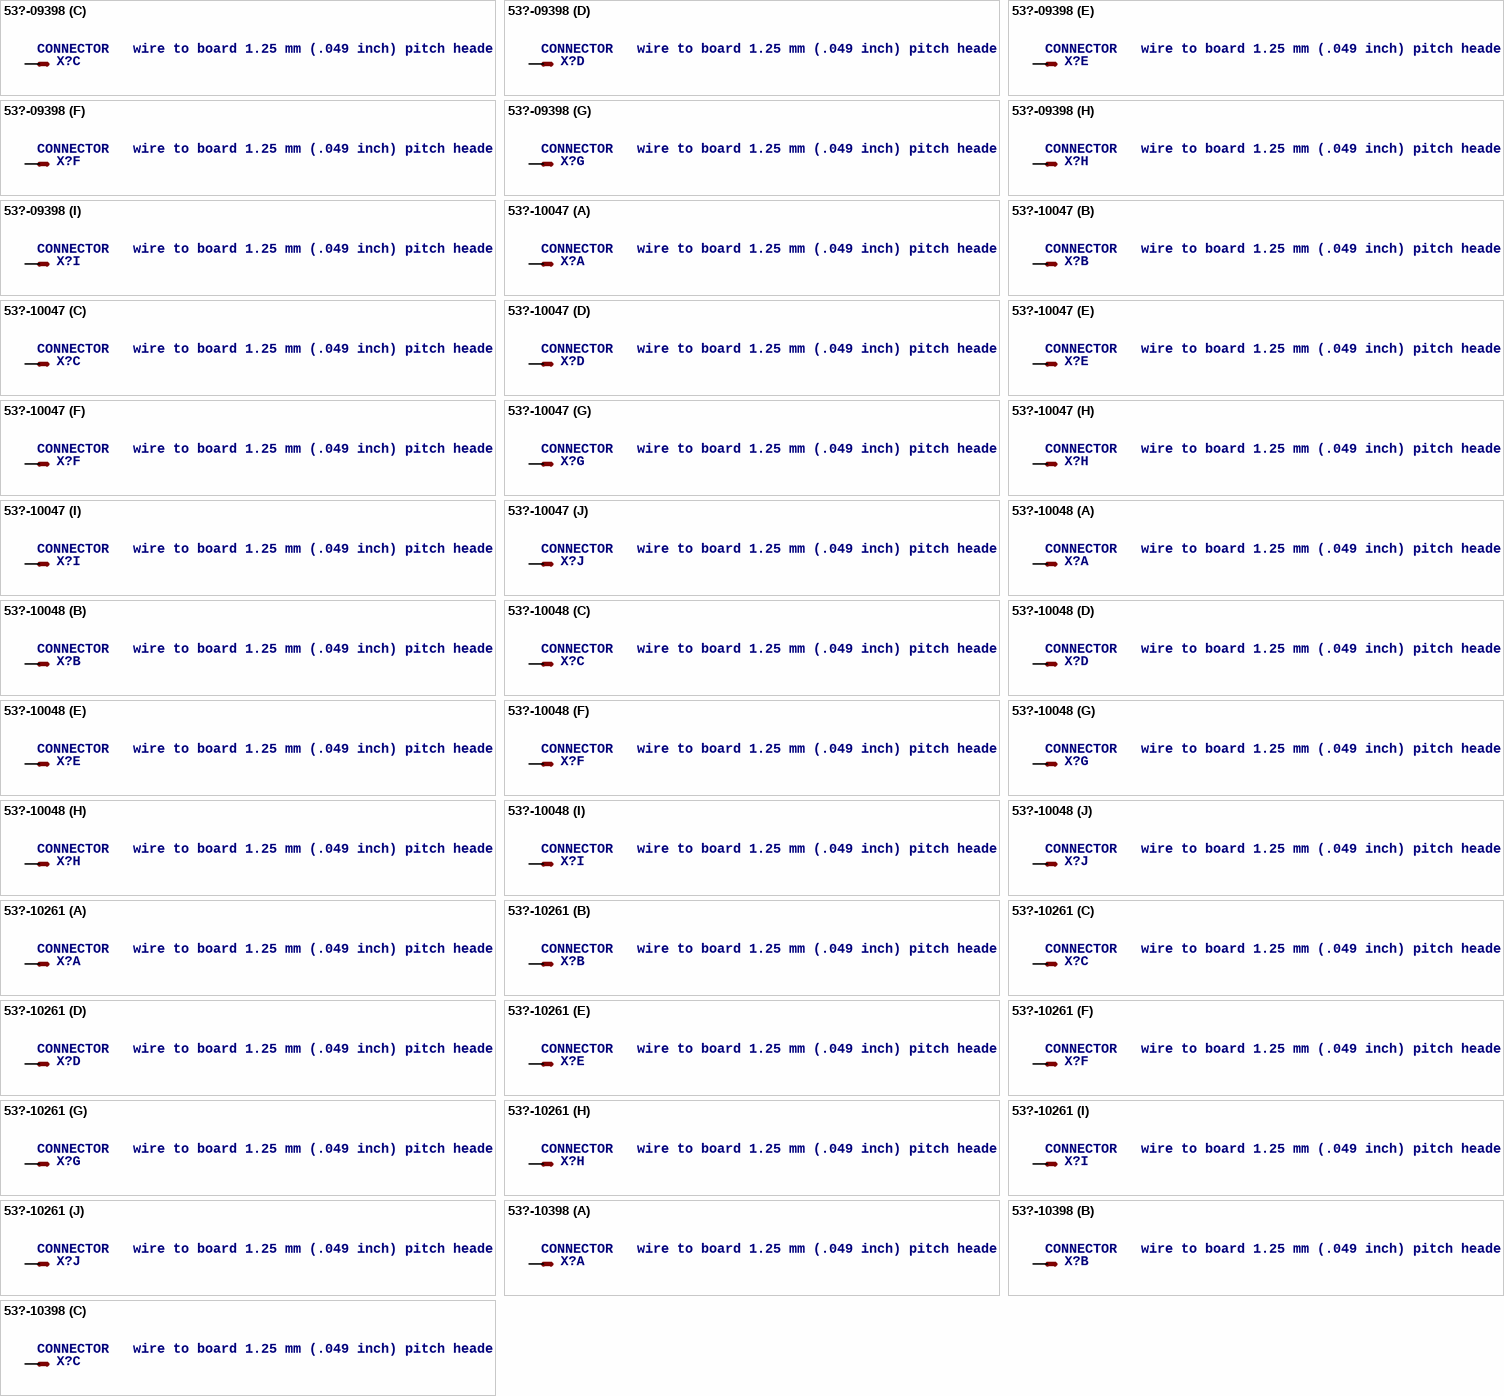
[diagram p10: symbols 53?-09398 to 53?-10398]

## 53?-09398
designator X?, comment CONNECTOR   wire to board 1.25 mm (.049 inch) pitch header
footprint 53398-09
part A pins: 1 S
part B pins: 2 S
part C pins: 3 S
part D pins: 4 S
part E pins: 5 S
part F pins: 6 S
part G pins: 7 S
part H pins: 8 S
part I pins: 9 S

## 53?-10047
designator X?, comment CONNECTOR   wire to board 1.25 mm (.049 inch) pitch header
MPN: 53047-1010; MF: MOLEX
footprint 53047-10
part A pins: 1 S
part B pins: 2 S
part C pins: 3 S
part D pins: 4 S
part E pins: 5 S
part F pins: 6 S
part G pins: 7 S
part H pins: 8 S
part I pins: 9 S
part J pins: 10 S

## 53?-10048
designator X?, comment CONNECTOR   wire to board 1.25 mm (.049 inch) pitch header
MPN: 53048-1010
footprint 53048-10
part A pins: 1 S
part B pins: 2 S
part C pins: 3 S
part D pins: 4 S
part E pins: 5 S
part F pins: 6 S
part G pins: 7 S
part H pins: 8 S
part I pins: 9 S
part J pins: 10 S

## 53?-10261
designator X?, comment CONNECTOR   wire to board 1.25 mm (.049 inch) pitch header
footprint 53261-10
part A pins: 1 S
part B pins: 2 S
part C pins: 3 S
part D pins: 4 S
part E pins: 5 S
part F pins: 6 S
part G pins: 7 S
part H pins: 8 S
part I pins: 9 S
part J pins: 10 S

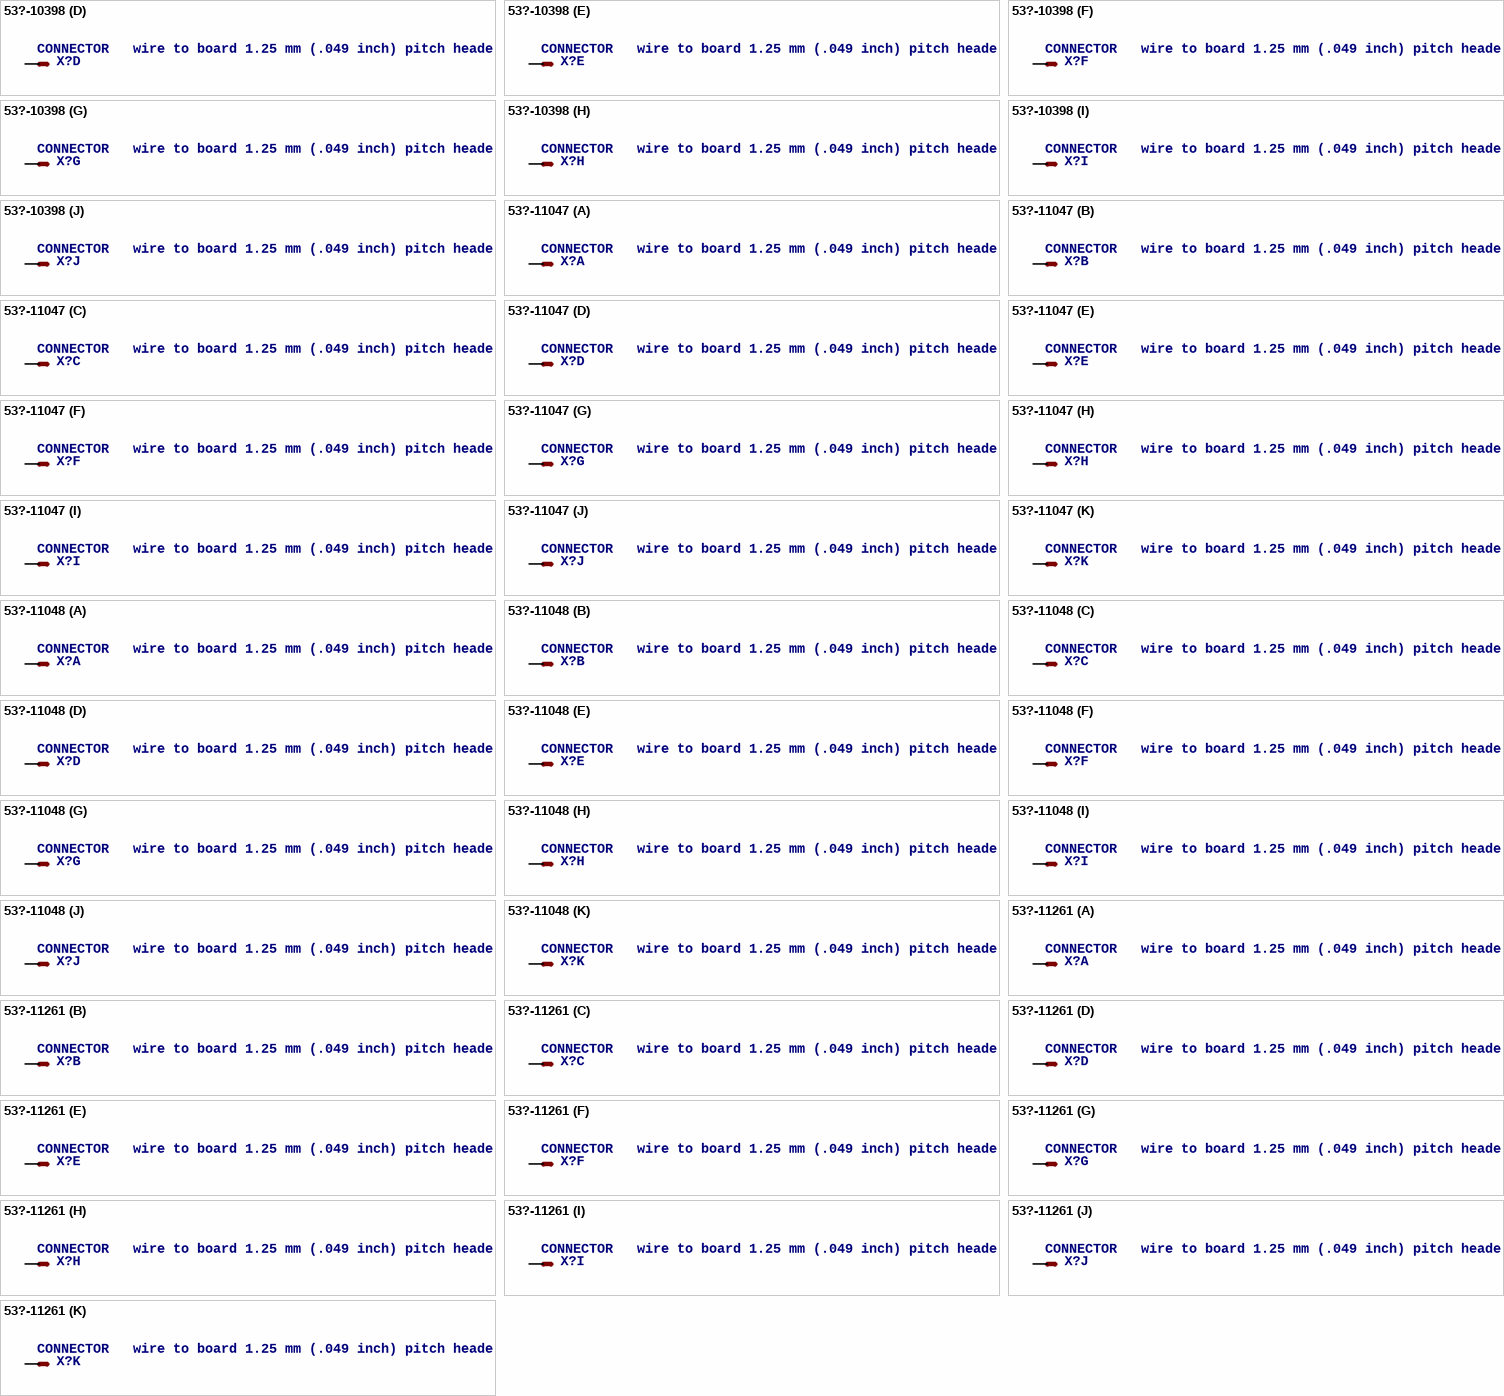
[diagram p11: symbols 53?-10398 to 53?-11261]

## 53?-10398
designator X?, comment CONNECTOR   wire to board 1.25 mm (.049 inch) pitch header
MPN: 53398-1071; MF: MOLEX
footprint 53398-10
part A pins: 1 S
part B pins: 2 S
part C pins: 3 S
part D pins: 4 S
part E pins: 5 S
part F pins: 6 S
part G pins: 7 S
part H pins: 8 S
part I pins: 9 S
part J pins: 10 S

## 53?-11047
designator X?, comment CONNECTOR   wire to board 1.25 mm (.049 inch) pitch header
MPN: 53047-1110; MF: WALDOM/MOLEX
footprint 53047-11
part A pins: 1 S
part B pins: 2 S
part C pins: 3 S
part D pins: 4 S
part E pins: 5 S
part F pins: 6 S
part G pins: 7 S
part H pins: 8 S
part I pins: 9 S
part J pins: 10 S
part K pins: 11 S

## 53?-11048
designator X?, comment CONNECTOR   wire to board 1.25 mm (.049 inch) pitch header
MPN: 53048-1110
footprint 53048-11
part A pins: 1 S
part B pins: 2 S
part C pins: 3 S
part D pins: 4 S
part E pins: 5 S
part F pins: 6 S
part G pins: 7 S
part H pins: 8 S
part I pins: 9 S
part J pins: 10 S
part K pins: 11 S

## 53?-11261
designator X?, comment CONNECTOR   wire to board 1.25 mm (.049 inch) pitch header
MPN: 53261-1171
footprint 53261-11
part A pins: 1 S
part B pins: 2 S
part C pins: 3 S
part D pins: 4 S
part E pins: 5 S
part F pins: 6 S
part G pins: 7 S
part H pins: 8 S
part I pins: 9 S
part J pins: 10 S
part K pins: 11 S

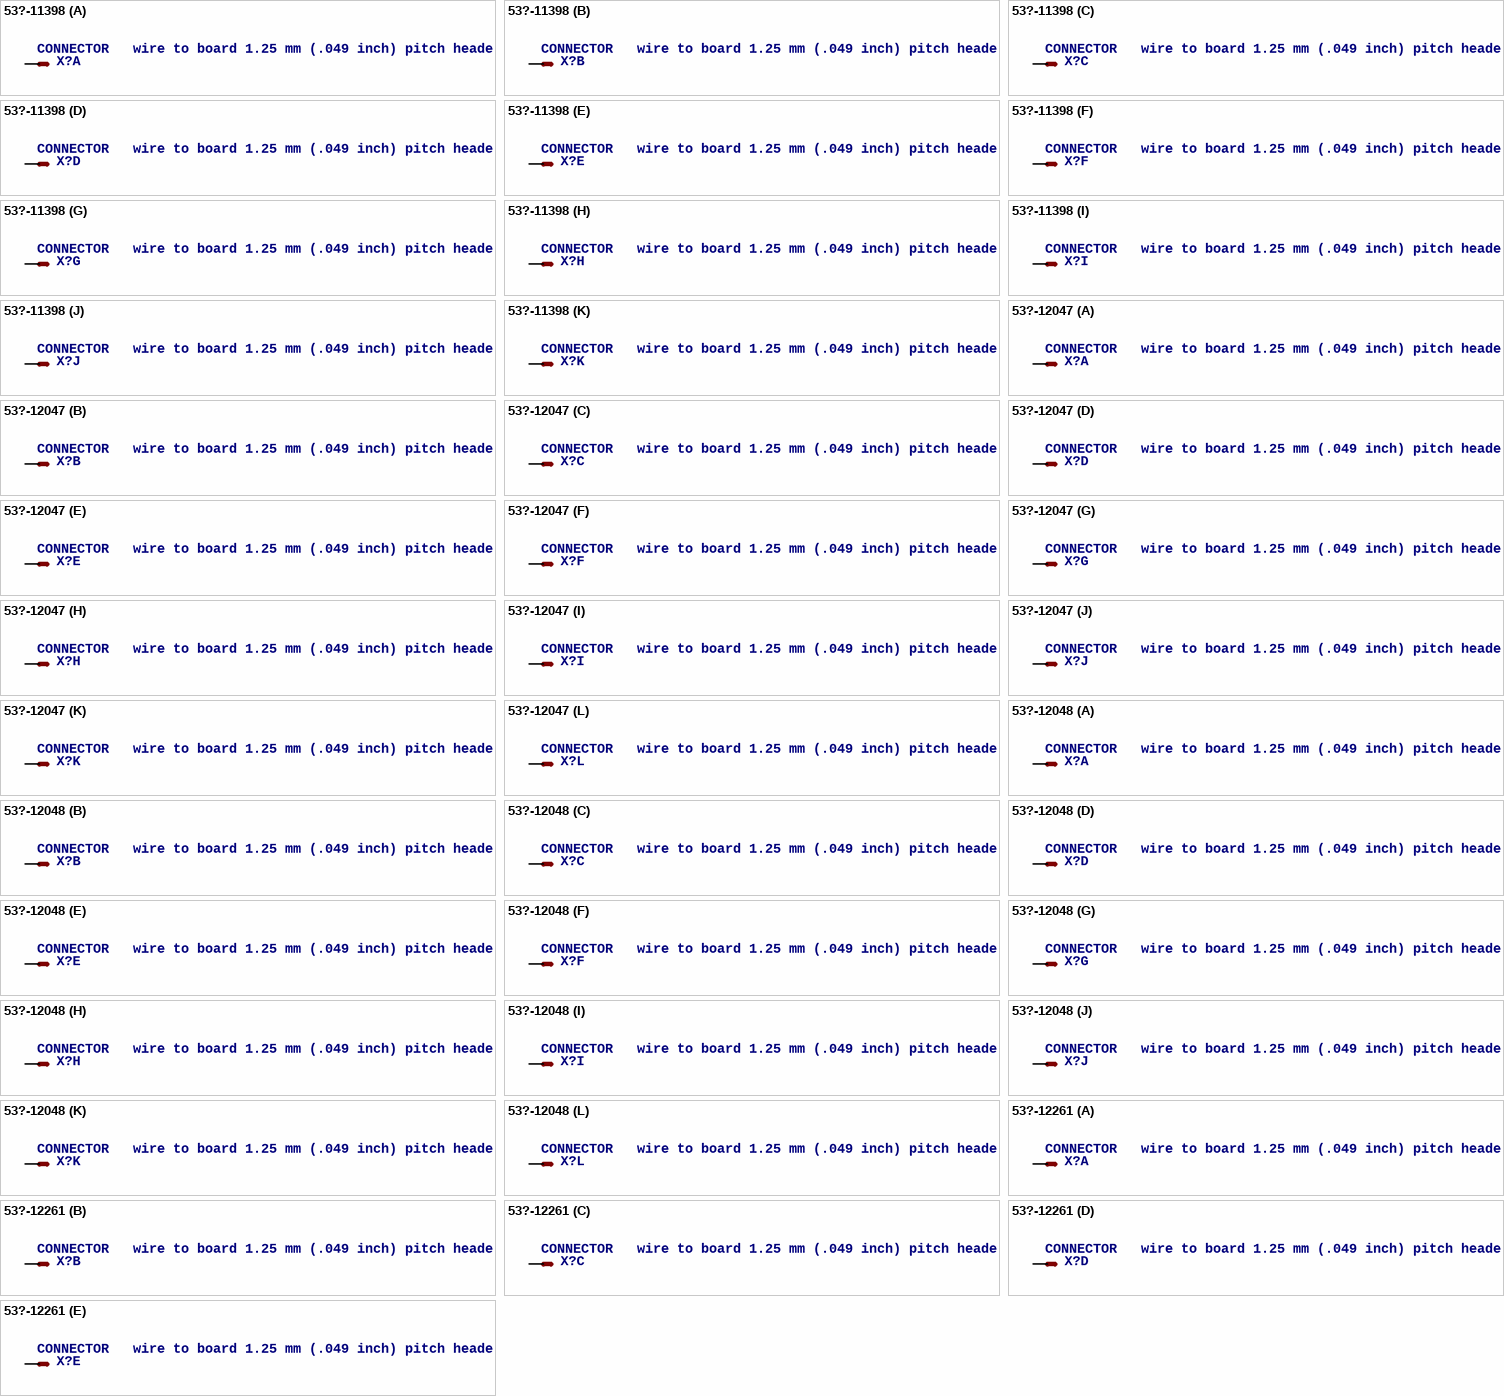
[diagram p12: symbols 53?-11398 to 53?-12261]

## 53?-11398
designator X?, comment CONNECTOR   wire to board 1.25 mm (.049 inch) pitch header
footprint 53398-11
part A pins: 1 S
part B pins: 2 S
part C pins: 3 S
part D pins: 4 S
part E pins: 5 S
part F pins: 6 S
part G pins: 7 S
part H pins: 8 S
part I pins: 9 S
part J pins: 10 S
part K pins: 11 S

## 53?-12047
designator X?, comment CONNECTOR   wire to board 1.25 mm (.049 inch) pitch header
MPN: 53047-1210; MF: WALDOM/MOLEX
footprint 53047-12
part A pins: 1 S
part B pins: 2 S
part C pins: 3 S
part D pins: 4 S
part E pins: 5 S
part F pins: 6 S
part G pins: 7 S
part H pins: 8 S
part I pins: 9 S
part J pins: 10 S
part K pins: 11 S
part L pins: 12 S

## 53?-12048
designator X?, comment CONNECTOR   wire to board 1.25 mm (.049 inch) pitch header
MPN: 53048-1210; MF: WALDOM/MOLEX
footprint 53048-12
part A pins: 1 S
part B pins: 2 S
part C pins: 3 S
part D pins: 4 S
part E pins: 5 S
part F pins: 6 S
part G pins: 7 S
part H pins: 8 S
part I pins: 9 S
part J pins: 10 S
part K pins: 11 S
part L pins: 12 S

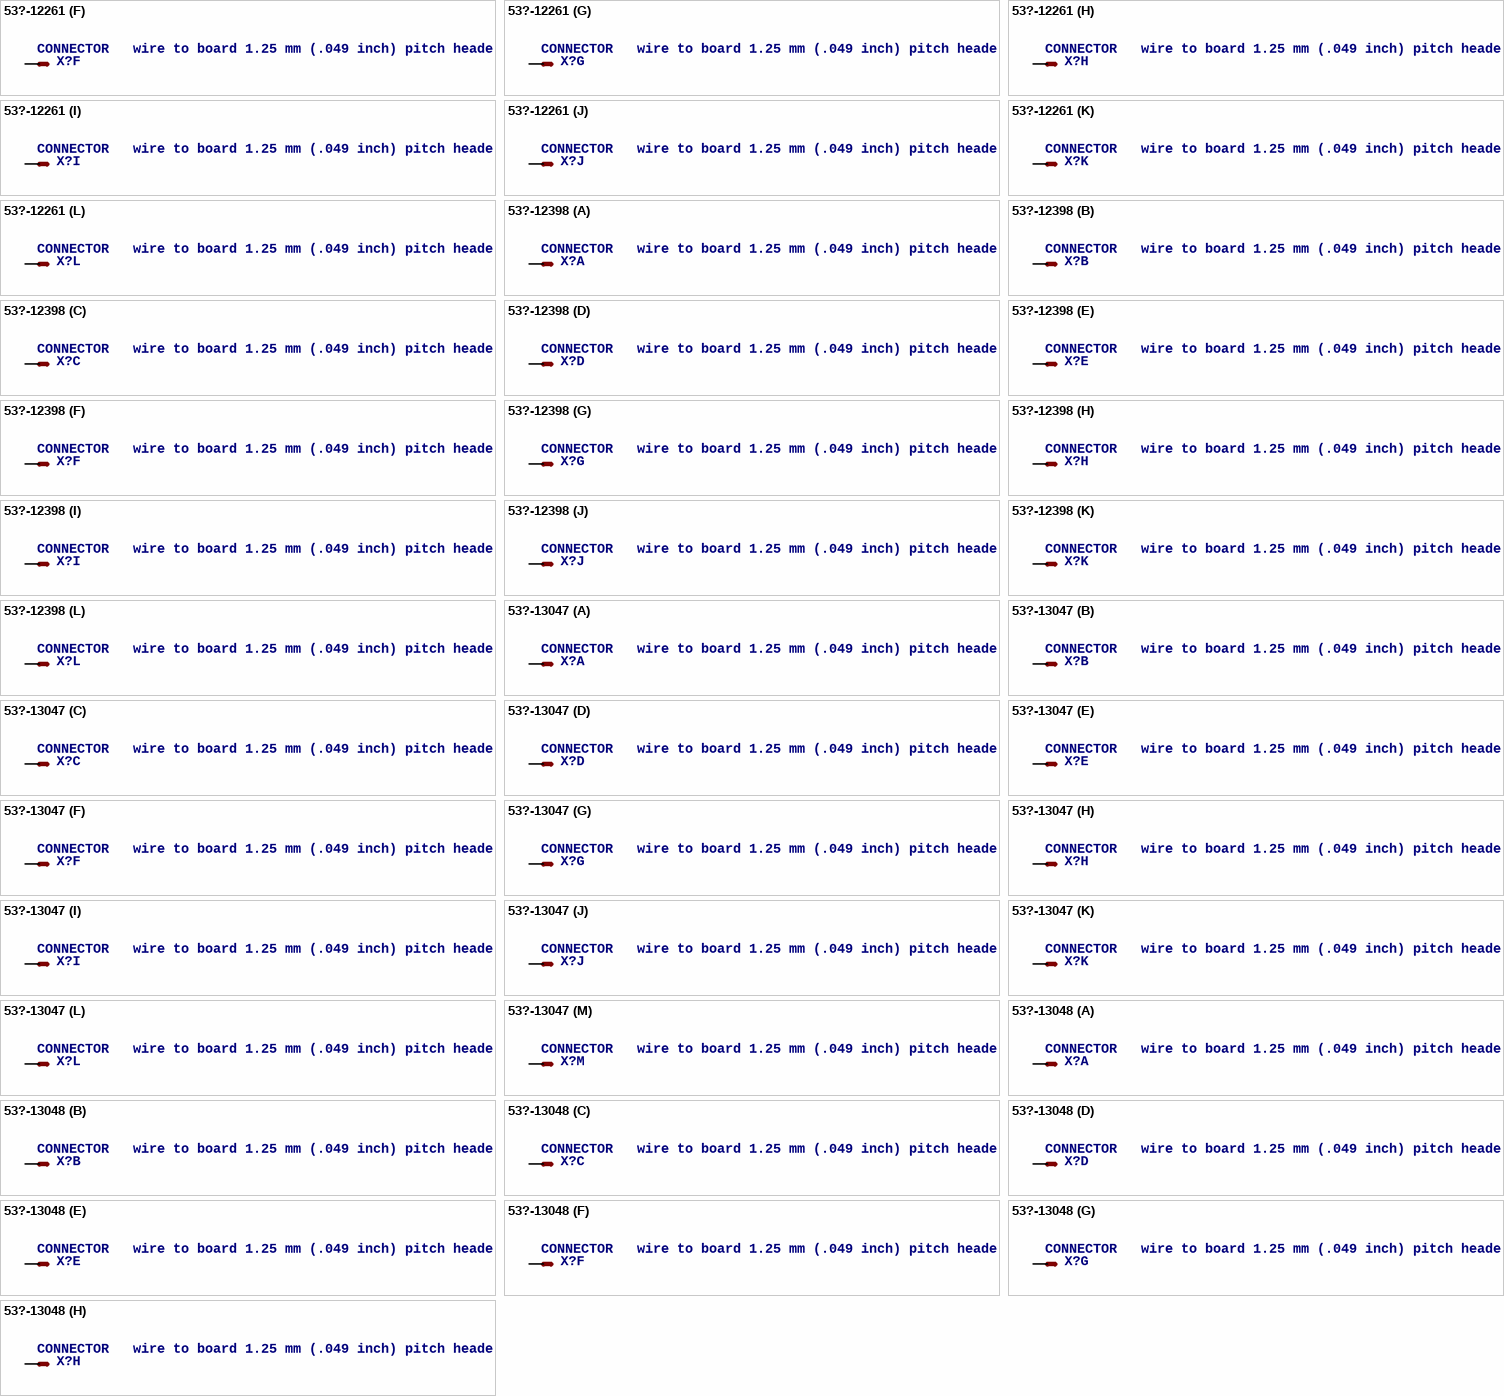
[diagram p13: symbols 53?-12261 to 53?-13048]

## 53?-12261
designator X?, comment CONNECTOR   wire to board 1.25 mm (.049 inch) pitch header
MPN: 53261-1271; MF: MOLEX
footprint 53261-12
part A pins: 1 S
part B pins: 2 S
part C pins: 3 S
part D pins: 4 S
part E pins: 5 S
part F pins: 6 S
part G pins: 7 S
part H pins: 8 S
part I pins: 9 S
part J pins: 10 S
part K pins: 11 S
part L pins: 12 S

## 53?-12398
designator X?, comment CONNECTOR   wire to board 1.25 mm (.049 inch) pitch header
footprint 53398-12
part A pins: 1 S
part B pins: 2 S
part C pins: 3 S
part D pins: 4 S
part E pins: 5 S
part F pins: 6 S
part G pins: 7 S
part H pins: 8 S
part I pins: 9 S
part J pins: 10 S
part K pins: 11 S
part L pins: 12 S

## 53?-13047
designator X?, comment CONNECTOR   wire to board 1.25 mm (.049 inch) pitch header
MPN: 53047-1310-C
footprint 53047-13
part A pins: 1 S
part B pins: 2 S
part C pins: 3 S
part D pins: 4 S
part E pins: 5 S
part F pins: 6 S
part G pins: 7 S
part H pins: 8 S
part I pins: 9 S
part J pins: 10 S
part K pins: 11 S
part L pins: 12 S
part M pins: 13 S

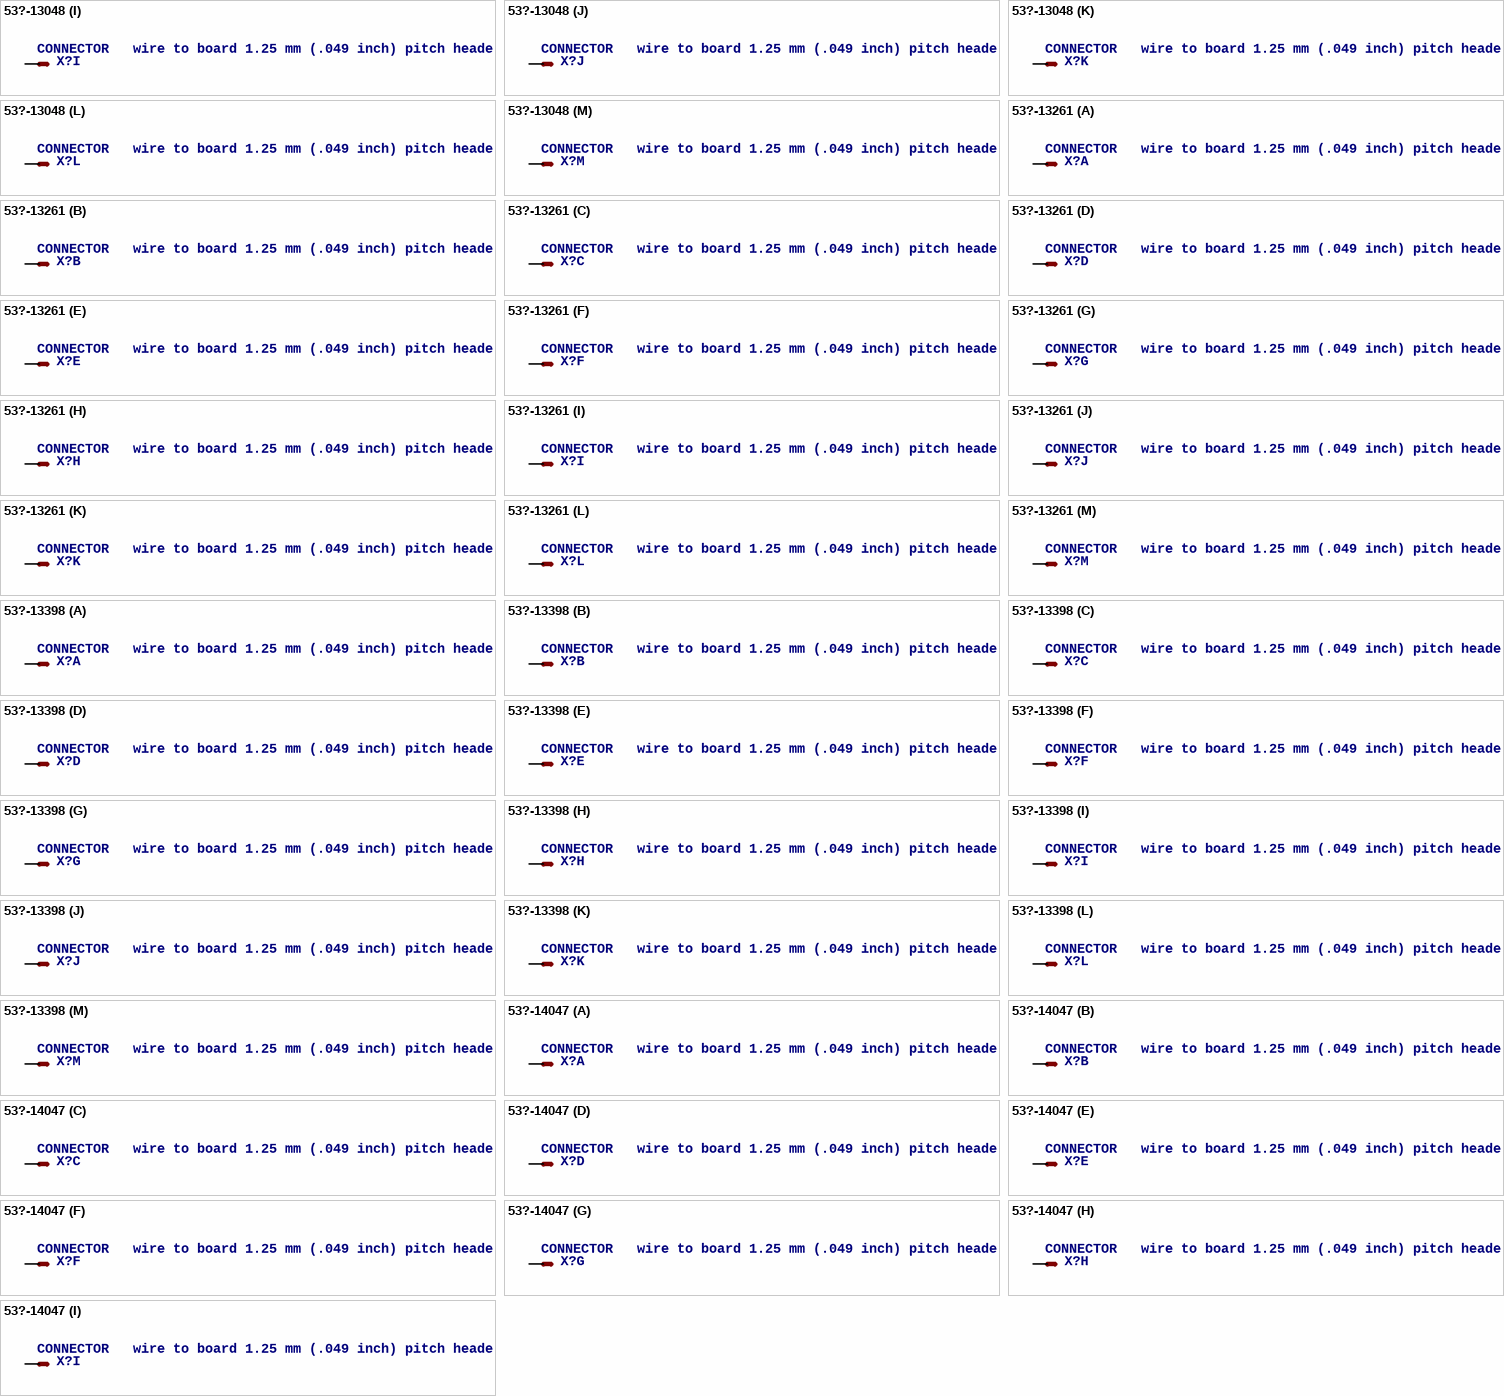
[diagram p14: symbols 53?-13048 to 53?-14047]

## 53?-13048
designator X?, comment CONNECTOR   wire to board 1.25 mm (.049 inch) pitch header
MPN: 53048-1310-C
footprint 53048-13
part A pins: 1 S
part B pins: 2 S
part C pins: 3 S
part D pins: 4 S
part E pins: 5 S
part F pins: 6 S
part G pins: 7 S
part H pins: 8 S
part I pins: 9 S
part J pins: 10 S
part K pins: 11 S
part L pins: 12 S
part M pins: 13 S

## 53?-13261
designator X?, comment CONNECTOR   wire to board 1.25 mm (.049 inch) pitch header
MPN: 53261-1371
footprint 53261-13
part A pins: 1 S
part B pins: 2 S
part C pins: 3 S
part D pins: 4 S
part E pins: 5 S
part F pins: 6 S
part G pins: 7 S
part H pins: 8 S
part I pins: 9 S
part J pins: 10 S
part K pins: 11 S
part L pins: 12 S
part M pins: 13 S

## 53?-13398
designator X?, comment CONNECTOR   wire to board 1.25 mm (.049 inch) pitch header
footprint 53398-13
part A pins: 1 S
part B pins: 2 S
part C pins: 3 S
part D pins: 4 S
part E pins: 5 S
part F pins: 6 S
part G pins: 7 S
part H pins: 8 S
part I pins: 9 S
part J pins: 10 S
part K pins: 11 S
part L pins: 12 S
part M pins: 13 S

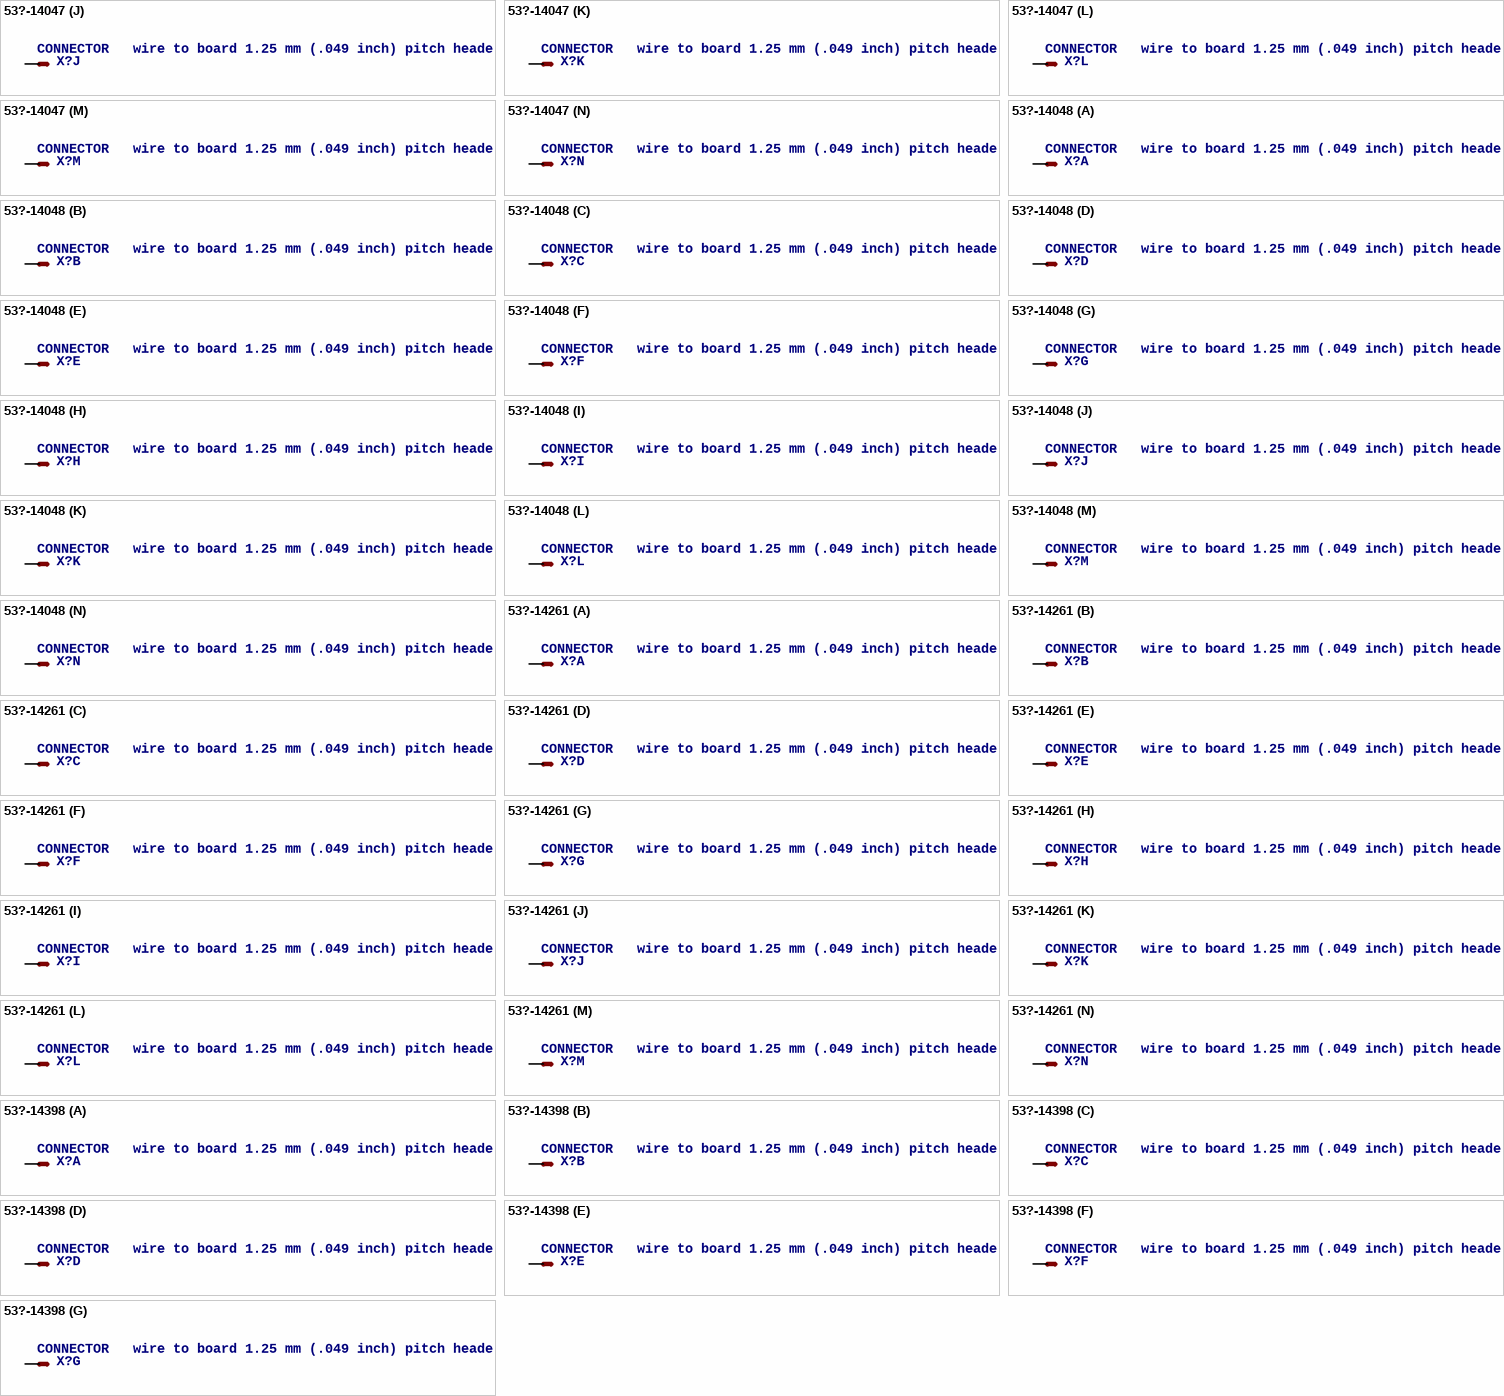
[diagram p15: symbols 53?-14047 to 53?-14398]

## 53?-14047
designator X?, comment CONNECTOR   wire to board 1.25 mm (.049 inch) pitch header
MPN: 53047-1410
footprint 53047-14
part A pins: 1 S
part B pins: 2 S
part C pins: 3 S
part D pins: 4 S
part E pins: 5 S
part F pins: 6 S
part G pins: 7 S
part H pins: 8 S
part I pins: 9 S
part J pins: 10 S
part K pins: 11 S
part L pins: 12 S
part M pins: 13 S
part N pins: 14 S

## 53?-14048
designator X?, comment CONNECTOR   wire to board 1.25 mm (.049 inch) pitch header
MPN: 53048-1410
footprint 53048-14
part A pins: 1 S
part B pins: 2 S
part C pins: 3 S
part D pins: 4 S
part E pins: 5 S
part F pins: 6 S
part G pins: 7 S
part H pins: 8 S
part I pins: 9 S
part J pins: 10 S
part K pins: 11 S
part L pins: 12 S
part M pins: 13 S
part N pins: 14 S

## 53?-14261
designator X?, comment CONNECTOR   wire to board 1.25 mm (.049 inch) pitch header
footprint 53261-14
part A pins: 1 S
part B pins: 2 S
part C pins: 3 S
part D pins: 4 S
part E pins: 5 S
part F pins: 6 S
part G pins: 7 S
part H pins: 8 S
part I pins: 9 S
part J pins: 10 S
part K pins: 11 S
part L pins: 12 S
part M pins: 13 S
part N pins: 14 S

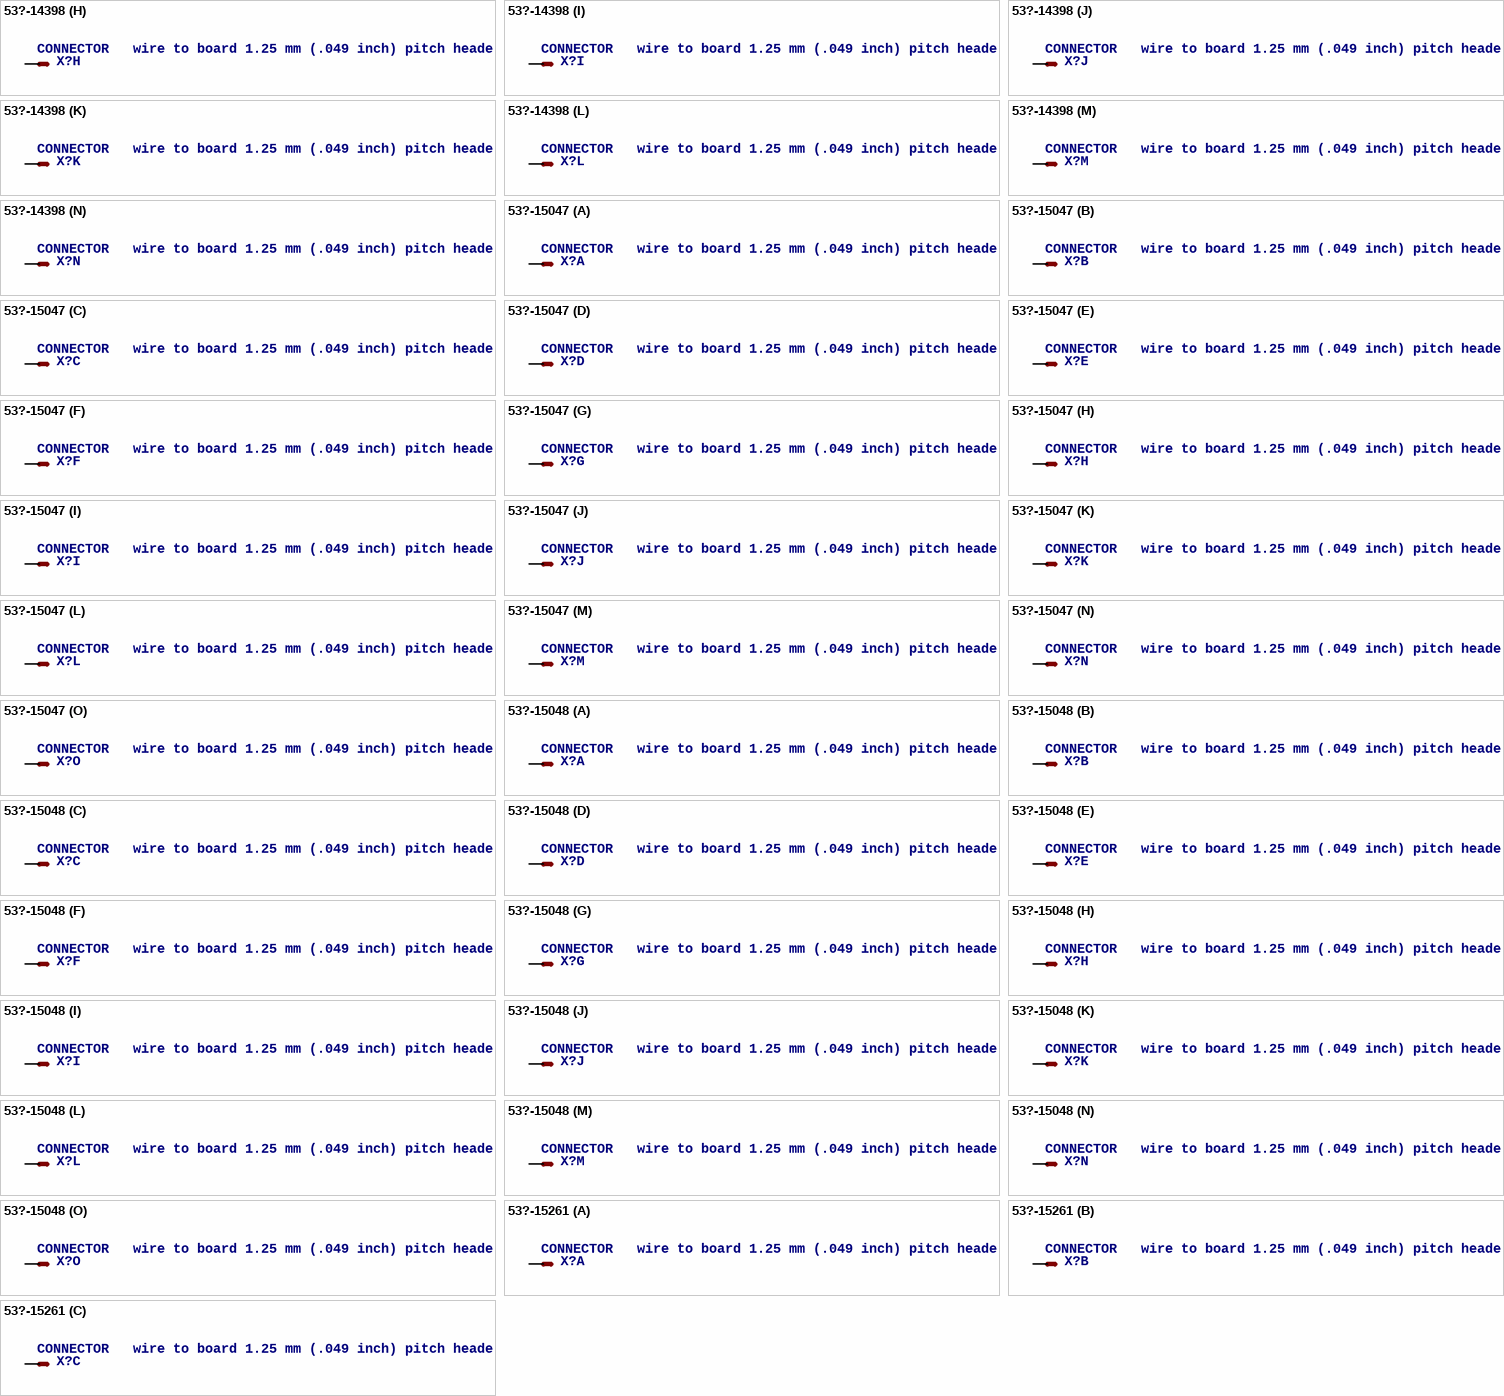
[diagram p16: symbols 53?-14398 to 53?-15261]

## 53?-14398
designator X?, comment CONNECTOR   wire to board 1.25 mm (.049 inch) pitch header
footprint 53398-14
part A pins: 1 S
part B pins: 2 S
part C pins: 3 S
part D pins: 4 S
part E pins: 5 S
part F pins: 6 S
part G pins: 7 S
part H pins: 8 S
part I pins: 9 S
part J pins: 10 S
part K pins: 11 S
part L pins: 12 S
part M pins: 13 S
part N pins: 14 S

## 53?-15047
designator X?, comment CONNECTOR   wire to board 1.25 mm (.049 inch) pitch header
MPN: 53047-1510-C
footprint 53047-15
part A pins: 1 S
part B pins: 2 S
part C pins: 3 S
part D pins: 4 S
part E pins: 5 S
part F pins: 6 S
part G pins: 7 S
part H pins: 8 S
part I pins: 9 S
part J pins: 10 S
part K pins: 11 S
part L pins: 12 S
part M pins: 13 S
part N pins: 14 S
part O pins: 15 S

## 53?-15048
designator X?, comment CONNECTOR   wire to board 1.25 mm (.049 inch) pitch header
MPN: 53048-1510
footprint 53048-15
part A pins: 1 S
part B pins: 2 S
part C pins: 3 S
part D pins: 4 S
part E pins: 5 S
part F pins: 6 S
part G pins: 7 S
part H pins: 8 S
part I pins: 9 S
part J pins: 10 S
part K pins: 11 S
part L pins: 12 S
part M pins: 13 S
part N pins: 14 S
part O pins: 15 S

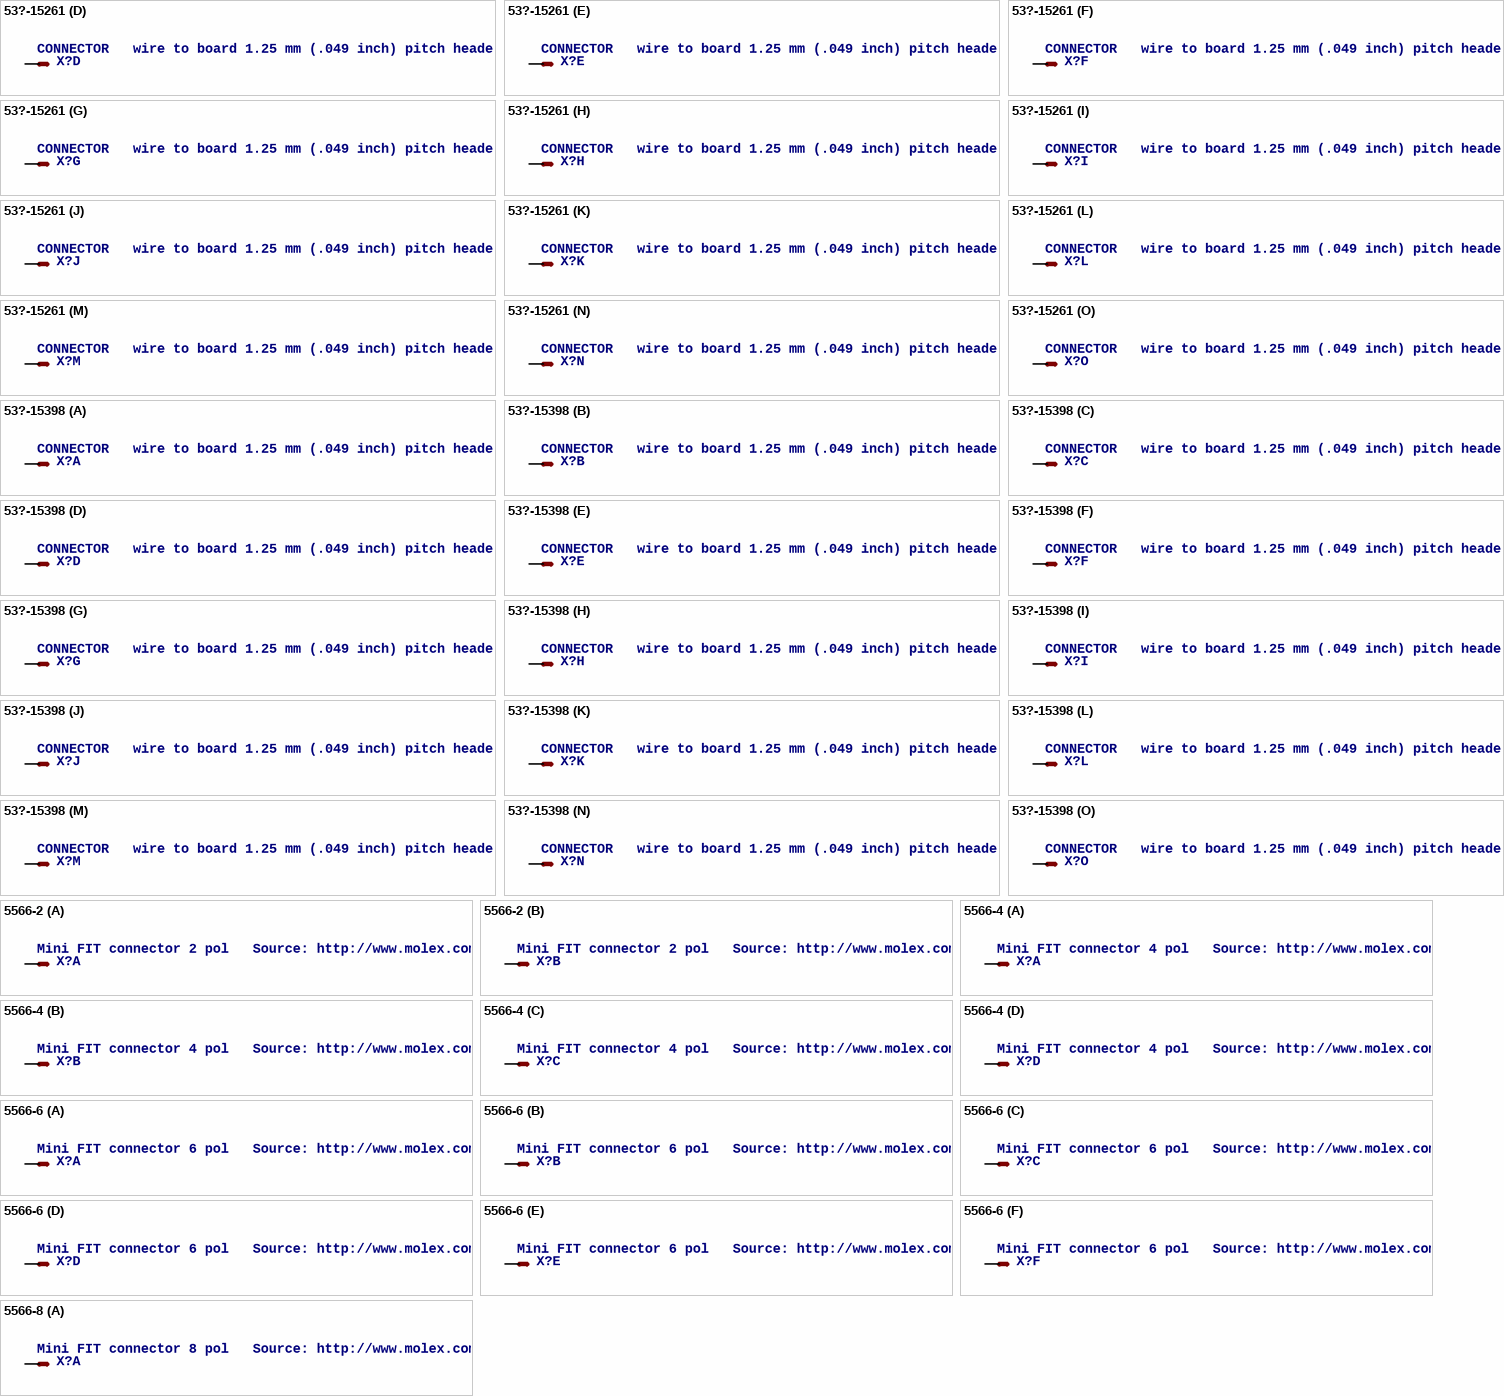
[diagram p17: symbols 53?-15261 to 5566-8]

## 53?-15261
designator X?, comment CONNECTOR   wire to board 1.25 mm (.049 inch) pitch header
footprint 53261-15
part A pins: 1 S
part B pins: 2 S
part C pins: 3 S
part D pins: 4 S
part E pins: 5 S
part F pins: 6 S
part G pins: 7 S
part H pins: 8 S
part I pins: 9 S
part J pins: 10 S
part K pins: 11 S
part L pins: 12 S
part M pins: 13 S
part N pins: 14 S
part O pins: 15 S

## 53?-15398
designator X?, comment CONNECTOR   wire to board 1.25 mm (.049 inch) pitch header
MPN: 53398-1590; MF: MOLEX
footprint 53398-15
part A pins: 1 S
part B pins: 2 S
part C pins: 3 S
part D pins: 4 S
part E pins: 5 S
part F pins: 6 S
part G pins: 7 S
part H pins: 8 S
part I pins: 9 S
part J pins: 10 S
part K pins: 11 S
part L pins: 12 S
part M pins: 13 S
part N pins: 14 S
part O pins: 15 S

## 5566-2
designator X?, comment Mini FIT connector 2 pol   Source: http://www.molex.com
footprint 5566-2
part A pins: 1 S
part B pins: 2 S

## 5566-4
designator X?, comment Mini FIT connector 4 pol   Source: http://www.molex.com
footprint 5566-4
part A pins: 1 S
part B pins: 2 S
part C pins: 3 S
part D pins: 4 S

## 5566-6
designator X?, comment Mini FIT connector 6 pol   Source: http://www.molex.com
MPN: 95566-61002
footprint 5566-6
part A pins: 1 S
part B pins: 2 S
part C pins: 3 S
part D pins: 4 S
part E pins: 5 S
part F pins: 6 S

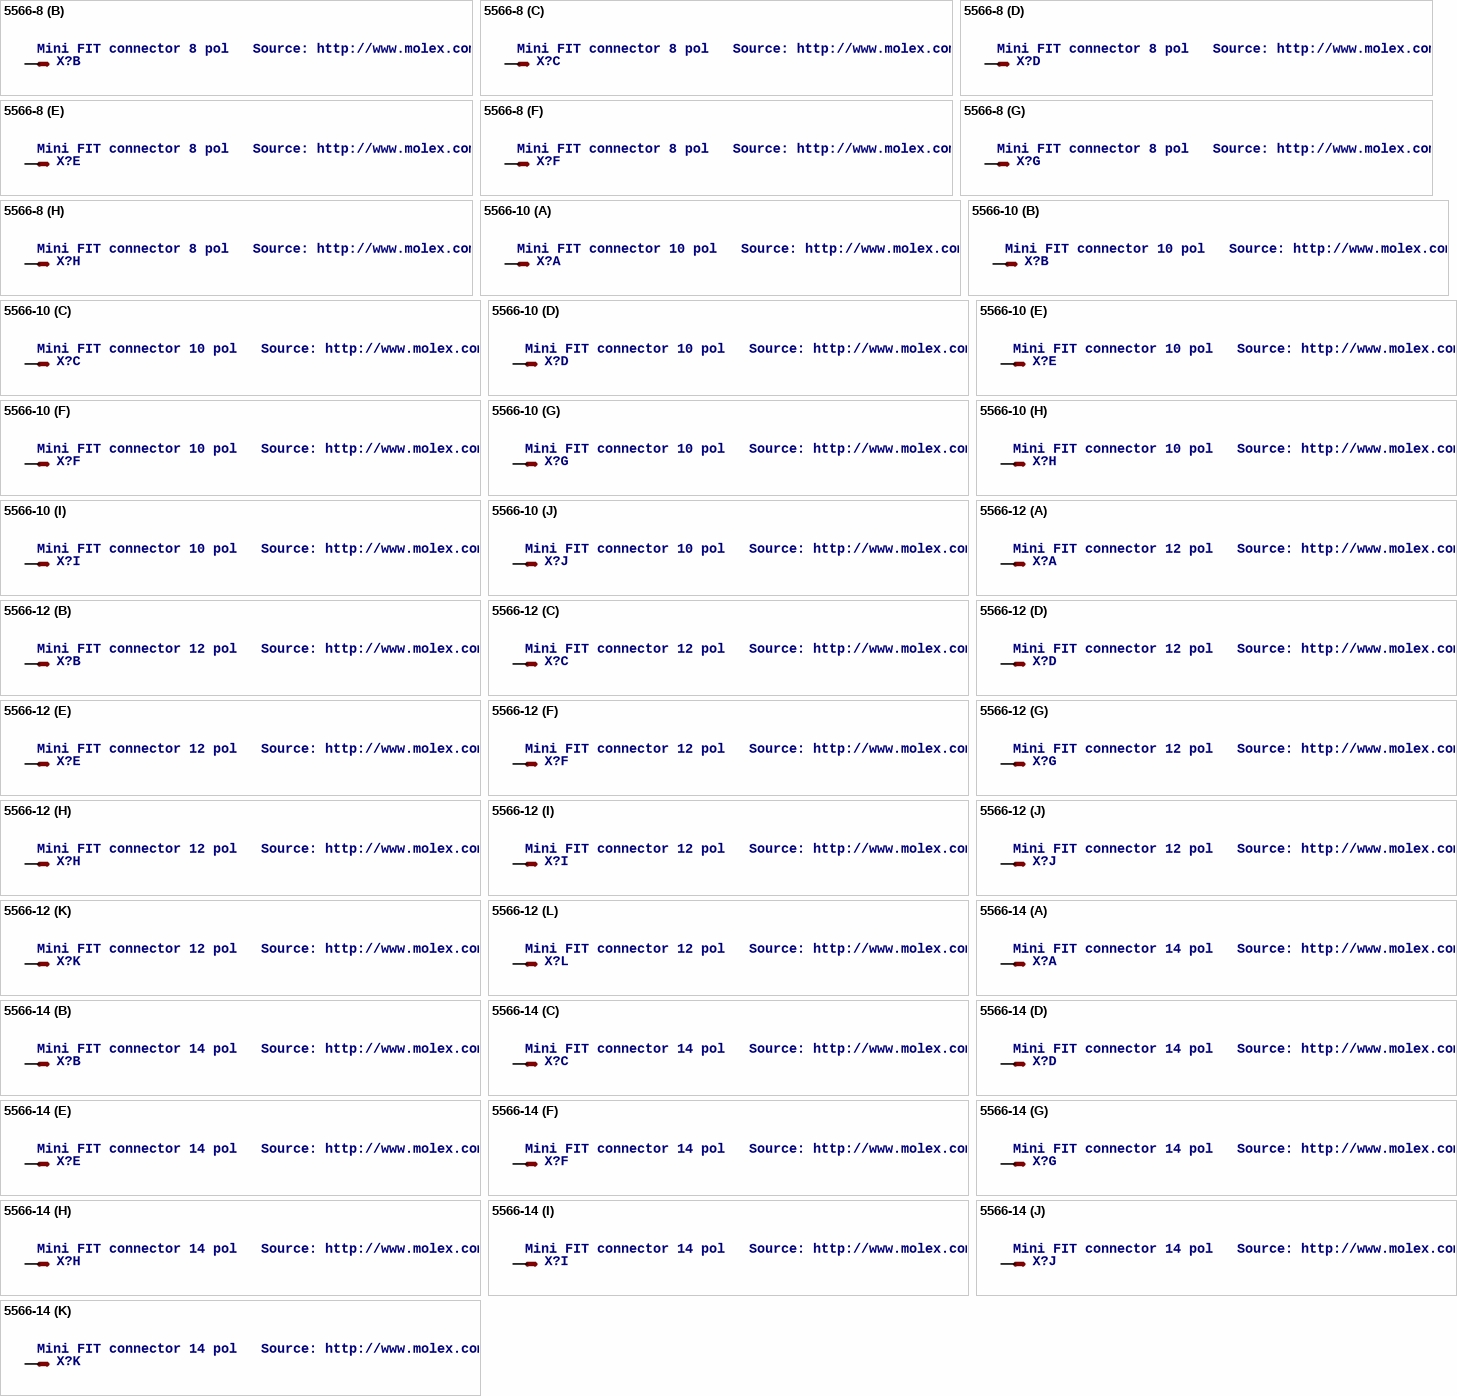
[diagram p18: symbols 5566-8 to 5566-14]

## 5566-8
designator X?, comment Mini FIT connector 8 pol   Source: http://www.molex.com
footprint 5566-8
part A pins: 1 S
part B pins: 2 S
part C pins: 3 S
part D pins: 4 S
part E pins: 5 S
part F pins: 6 S
part G pins: 7 S
part H pins: 8 S

## 5566-10
designator X?, comment Mini FIT connector 10 pol   Source: http://www.molex.com
footprint 5566-10
part A pins: 1 S
part B pins: 2 S
part C pins: 3 S
part D pins: 4 S
part E pins: 5 S
part F pins: 6 S
part G pins: 7 S
part H pins: 8 S
part I pins: 9 S
part J pins: 10 S

## 5566-12
designator X?, comment Mini FIT connector 12 pol   Source: http://www.molex.com
footprint 5566-12
part A pins: 1 S
part B pins: 2 S
part C pins: 3 S
part D pins: 4 S
part E pins: 5 S
part F pins: 6 S
part G pins: 7 S
part H pins: 8 S
part I pins: 9 S
part J pins: 10 S
part K pins: 11 S
part L pins: 12 S

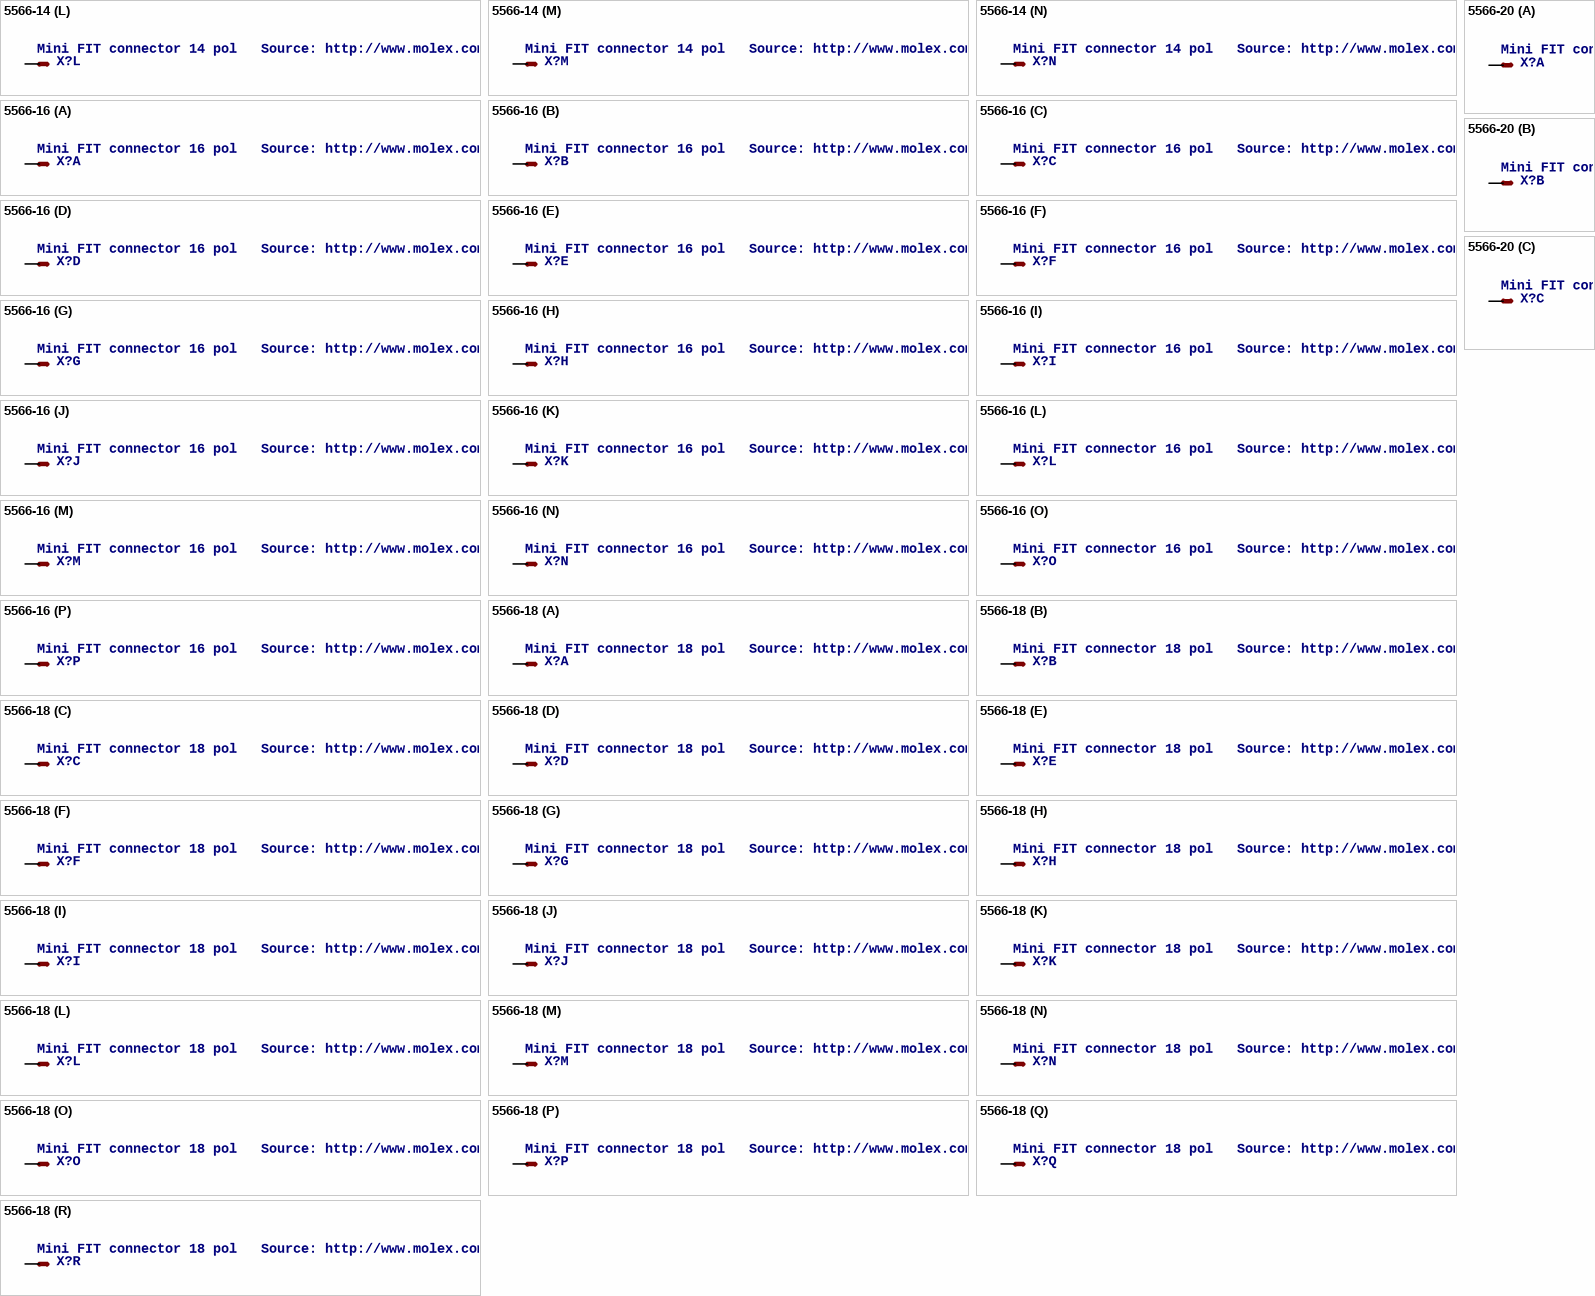
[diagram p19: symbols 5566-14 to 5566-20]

## 5566-14
designator X?, comment Mini FIT connector 14 pol   Source: http://www.molex.com
footprint 5566-14
part A pins: 1 S
part B pins: 2 S
part C pins: 3 S
part D pins: 4 S
part E pins: 5 S
part F pins: 6 S
part G pins: 7 S
part H pins: 8 S
part I pins: 9 S
part J pins: 10 S
part K pins: 11 S
part L pins: 12 S
part M pins: 13 S
part N pins: 14 S

## 5566-16
designator X?, comment Mini FIT connector 16 pol   Source: http://www.molex.com
footprint 5566-16
part A pins: 1 S
part B pins: 2 S
part C pins: 3 S
part D pins: 4 S
part E pins: 5 S
part F pins: 6 S
part G pins: 7 S
part H pins: 8 S
part I pins: 9 S
part J pins: 10 S
part K pins: 11 S
part L pins: 12 S
part M pins: 13 S
part N pins: 14 S
part O pins: 15 S
part P pins: 16 S

## 5566-18
designator X?, comment Mini FIT connector 18 pol   Source: http://www.molex.com
footprint 5566-18
part A pins: 1 S
part B pins: 2 S
part C pins: 3 S
part D pins: 4 S
part E pins: 5 S
part F pins: 6 S
part G pins: 7 S
part H pins: 8 S
part I pins: 9 S
part J pins: 10 S
part K pins: 11 S
part L pins: 12 S
part M pins: 13 S
part N pins: 14 S
part O pins: 15 S
part P pins: 16 S
part Q pins: 17 S
part R pins: 18 S

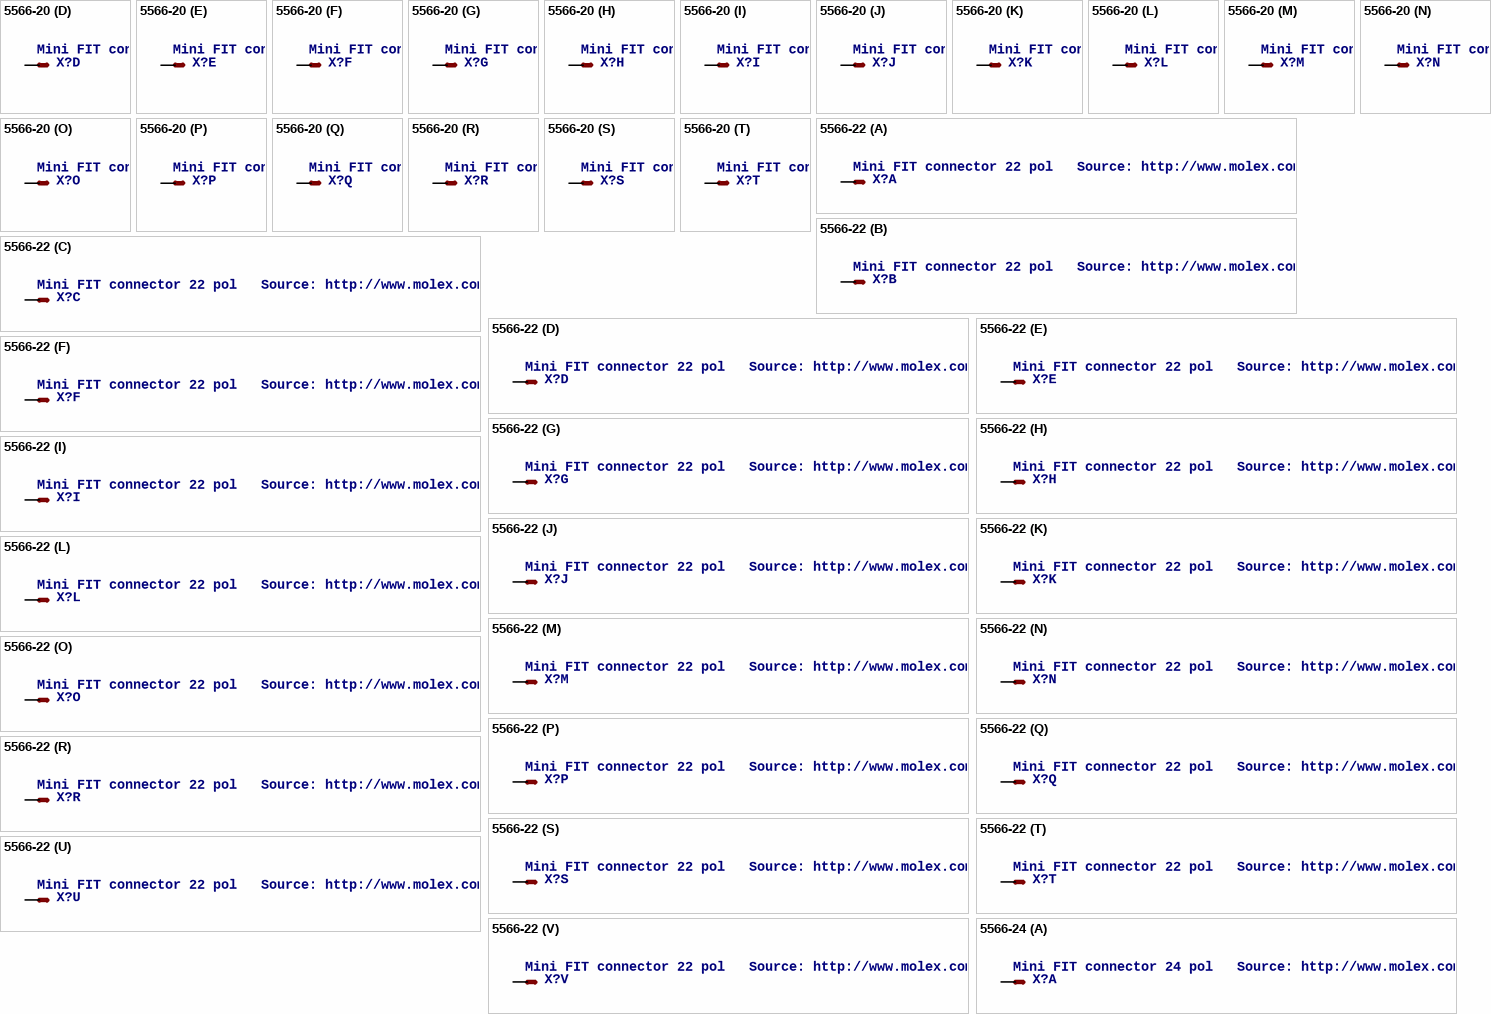
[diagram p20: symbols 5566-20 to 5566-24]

## 5566-20
designator X?, comment Mini FIT connector 20 pol   ATX PC-Motherboard Power connector Source: http://www.molex.com
footprint 5566-20
part A pins: 1 S
part B pins: 2 S
part C pins: 3 S
part D pins: 4 S
part E pins: 5 S
part F pins: 6 S
part G pins: 7 S
part H pins: 8 S
part I pins: 9 S
part J pins: 10 S
part K pins: 11 S
part L pins: 12 S
part M pins: 13 S
part N pins: 14 S
part O pins: 15 S
part P pins: 16 S
part Q pins: 17 S
part R pins: 18 S
part S pins: 19 S
part T pins: 20 S

## 5566-22
designator X?, comment Mini FIT connector 22 pol   Source: http://www.molex.com
footprint 5566-22
part A pins: 1 S
part B pins: 2 S
part C pins: 3 S
part D pins: 4 S
part E pins: 5 S
part F pins: 6 S
part G pins: 7 S
part H pins: 8 S
part I pins: 9 S
part J pins: 10 S
part K pins: 11 S
part L pins: 12 S
part M pins: 13 S
part N pins: 14 S
part O pins: 15 S
part P pins: 16 S
part Q pins: 17 S
part R pins: 18 S
part S pins: 19 S
part T pins: 20 S
part U pins: 21 S
part V pins: 22 S

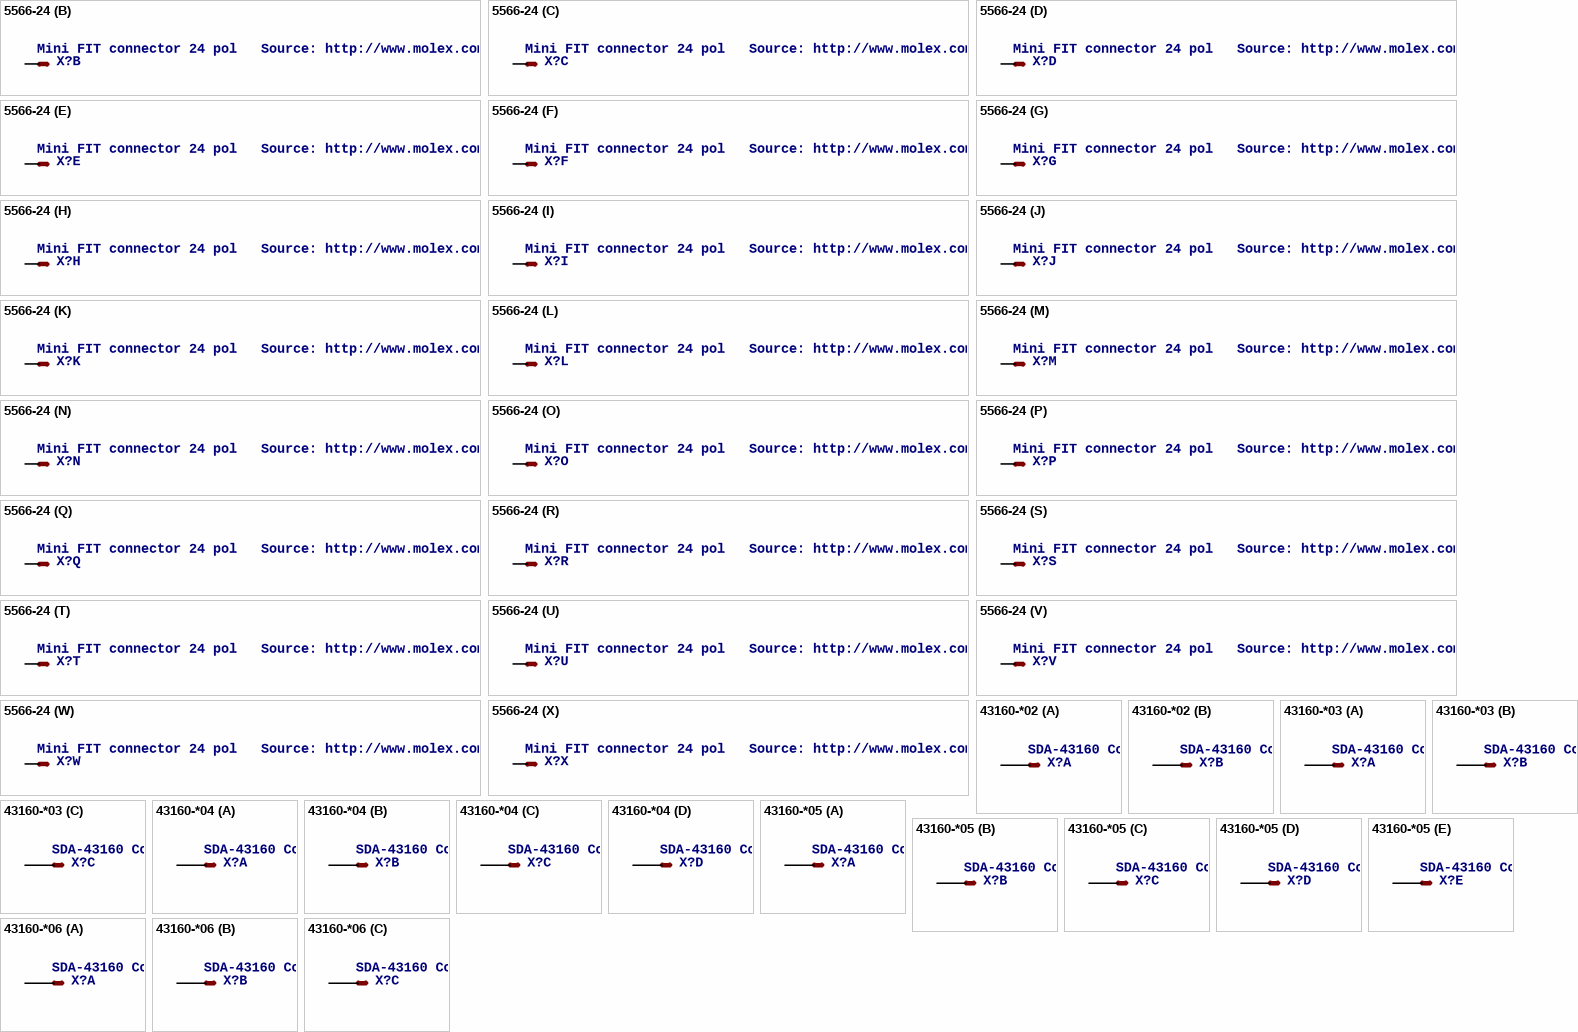
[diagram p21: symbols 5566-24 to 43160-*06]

## 5566-24
designator X?, comment Mini FIT connector 24 pol   Source: http://www.molex.com
footprint 5566-24
part A pins: 1 S
part B pins: 2 S
part C pins: 3 S
part D pins: 4 S
part E pins: 5 S
part F pins: 6 S
part G pins: 7 S
part H pins: 8 S
part I pins: 9 S
part J pins: 10 S
part K pins: 11 S
part L pins: 12 S
part M pins: 13 S
part N pins: 14 S
part O pins: 15 S
part P pins: 16 S
part Q pins: 17 S
part R pins: 18 S
part S pins: 19 S
part T pins: 20 S
part U pins: 21 S
part V pins: 22 S
part W pins: 23 S
part X pins: 24 S

## 43160-*02
designator X?, comment SDA-43160 Connector   Source: http://www.molex.com/pdm_docs/sd/431601306_sd.pdf
MPN: 43160-1102; MPN: 43160-1302; MPN: 43160-3102; MPN: 43160-5102; MPN: 43160-5302; MPN: 43160-7302; MF: WALDOM/MOLEX
footprint 43160-XX02
part A pins: 1@1 S@1, 1@2 S@2
part B pins: 2@1 S@1, 2@2 S@2

## 43160-*03
designator X?, comment SDA-43160 Connector   Source: http://www.molex.com/pdm_docs/sd/431601306_sd.pdf
MPN: 43160-1303; MPN: 43160-3103; MPN: 43160-5103; MPN: 43160-5303; MPN: 43160-7303; MF: WALDOM/MOLEX
footprint 43160-XX03
part A pins: 1@1 S@1, 1@2 S@2
part B pins: 2@1 S@1, 2@2 S@2
part C pins: 3@1 S@1, 3@2 S@2

## 43160-*04
designator X?, comment SDA-43160 Connector   Source: http://www.molex.com/pdm_docs/sd/431601306_sd.pdf
MPN: 43160-1104; MPN: 43160-1304; MPN: 43160-3104; MPN: 43160-5104; MPN: 43160-5304; MPN: 43160-7304; MF: WALDOM/MOLEX; MF: FARNELL
footprint 43160-XX04
part A pins: 1@1 S@1, 1@2 S@2
part B pins: 2@1 S@1, 2@2 S@2
part C pins: 3@1 S@1, 3@2 S@2
part D pins: 4@1 S@1, 4@2 S@2

## 43160-*05
designator X?, comment SDA-43160 Connector   Source: http://www.molex.com/pdm_docs/sd/431601306_sd.pdf
MPN: 43160-1105; MPN: 43160-1305; MPN: 43160-3105; MPN: 43160-5105; MPN: 43160-5305; MPN: 43160-7305; MF: WALDOM/MOLEX
footprint 43160-XX05
part A pins: 1@1 S@1, 1@2 S@2
part B pins: 2@1 S@1, 2@2 S@2
part C pins: 3@1 S@1, 3@2 S@2
part D pins: 4@1 S@1, 4@2 S@2
part E pins: 5@1 S@1, 5@2 S@2

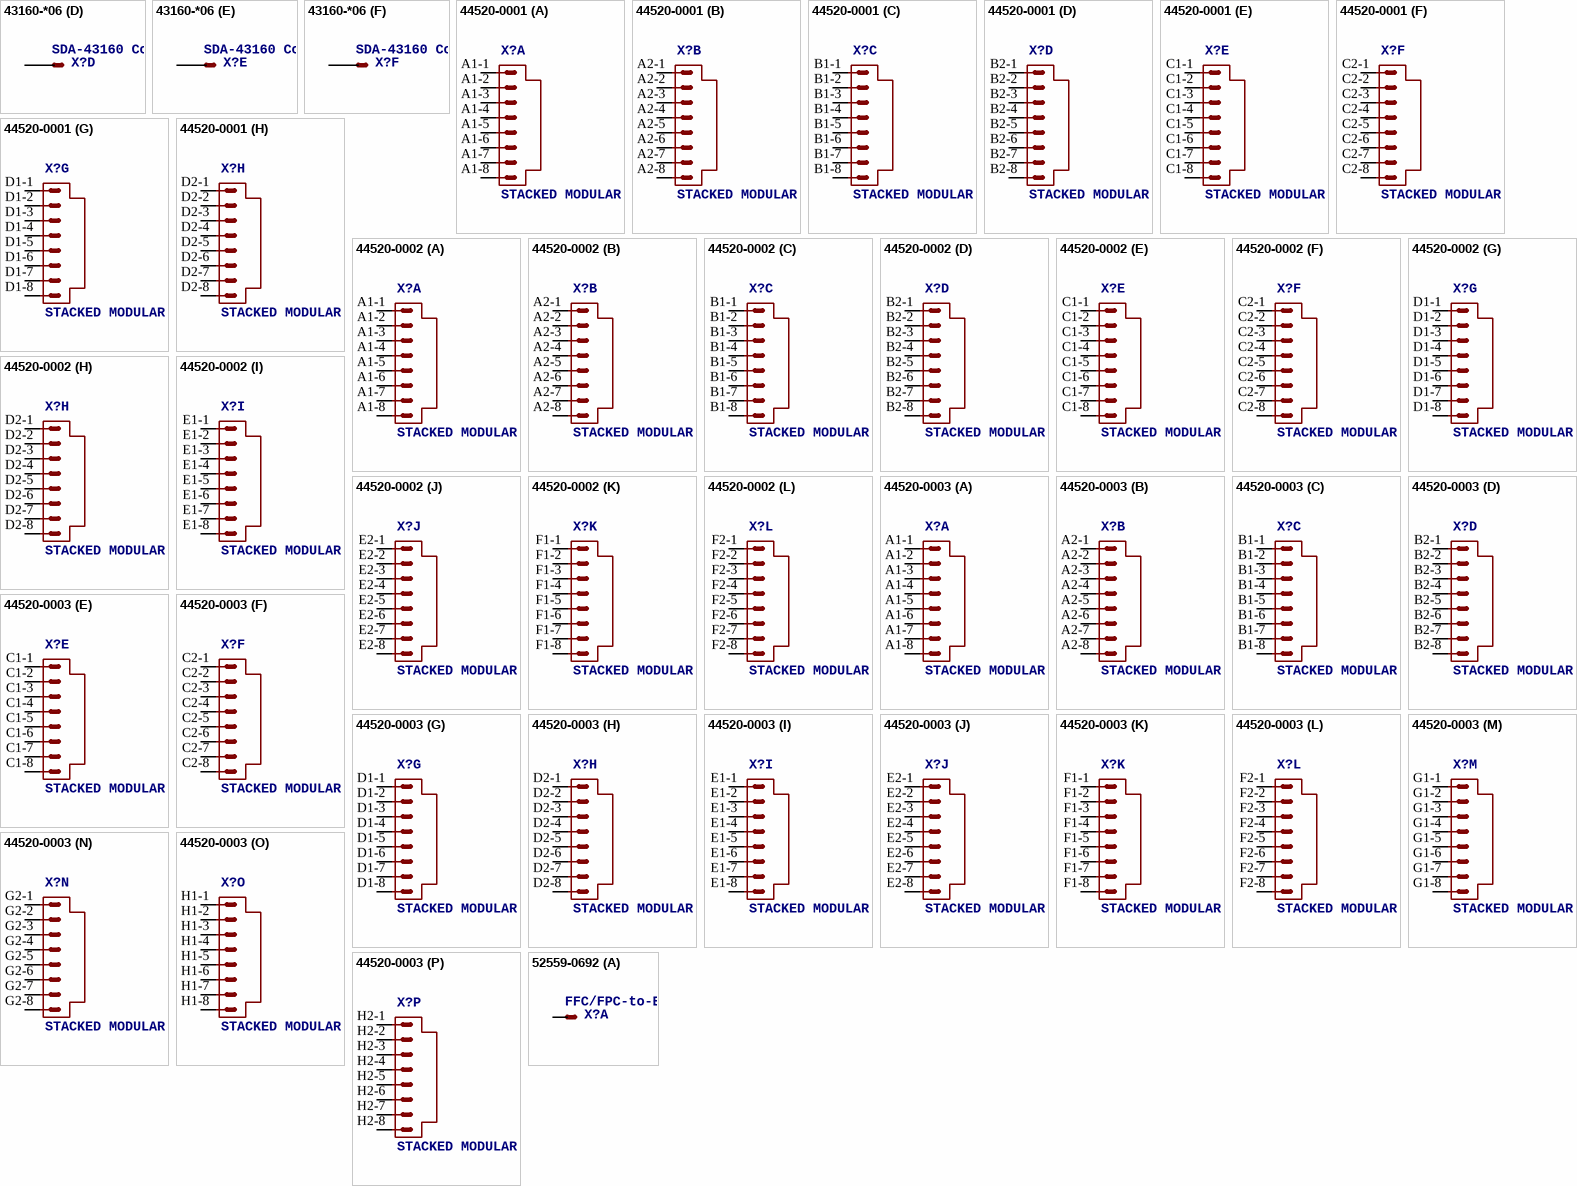
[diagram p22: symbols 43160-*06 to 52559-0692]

## 43160-*06
designator X?, comment SDA-43160 Connector   Source: http://www.molex.com/pdm_docs/sd/431601306_sd.pdf
MPN: 43160-1106; MPN: 43160-1306; MPN: 43160-3106; MPN: 43160-5106; MPN: 43160-5306; MPN: 43160-7306; MF: WALDOM/MOLEX
footprint 43160-XX06
part A pins: 1@1 S@1, 1@2 S@2
part B pins: 2@1 S@1, 2@2 S@2
part C pins: 3@1 S@1, 3@2 S@2
part D pins: 4@1 S@1, 4@2 S@2
part E pins: 5@1 S@1, 5@2 S@2
part F pins: 6@1 S@1, 6@2 S@2

## 44520-0001
designator X?, comment STACKED MODULAR JACK CATEGORY 5   Source: http://www.molex.com/pdm_docs/sd/445200006_sd.pdf
MPN: 44520-0001
footprint 44520-0001
part A pins: A1-1 1, A1-2 2, A1-3 3, A1-4 4, A1-5 5, A1-6 6, A1-7 7, A1-8 8
part B pins: A2-1 1, A2-2 2, A2-3 3, A2-4 4, A2-5 5, A2-6 6, A2-7 7, A2-8 8
part C pins: B1-1 1, B1-2 2, B1-3 3, B1-4 4, B1-5 5, B1-6 6, B1-7 7, B1-8 8
part D pins: B2-1 1, B2-2 2, B2-3 3, B2-4 4, B2-5 5, B2-6 6, B2-7 7, B2-8 8
part E pins: C1-1 1, C1-2 2, C1-3 3, C1-4 4, C1-5 5, C1-6 6, C1-7 7, C1-8 8
part F pins: C2-1 1, C2-2 2, C2-3 3, C2-4 4, C2-5 5, C2-6 6, C2-7 7, C2-8 8
part G pins: D1-1 1, D1-2 2, D1-3 3, D1-4 4, D1-5 5, D1-6 6, D1-7 7, D1-8 8
part H pins: D2-1 1, D2-2 2, D2-3 3, D2-4 4, D2-5 5, D2-6 6, D2-7 7, D2-8 8

## 44520-0002
designator X?, comment STACKED MODULAR JACK CATEGORY 5   Source: http://www.molex.com/pdm_docs/sd/445200006_sd.pdf
MPN: 44520-0002
footprint 44520-0002
part A pins: A1-1 1, A1-2 2, A1-3 3, A1-4 4, A1-5 5, A1-6 6, A1-7 7, A1-8 8
part B pins: A2-1 1, A2-2 2, A2-3 3, A2-4 4, A2-5 5, A2-6 6, A2-7 7, A2-8 8
part C pins: B1-1 1, B1-2 2, B1-3 3, B1-4 4, B1-5 5, B1-6 6, B1-7 7, B1-8 8
part D pins: B2-1 1, B2-2 2, B2-3 3, B2-4 4, B2-5 5, B2-6 6, B2-7 7, B2-8 8
part E pins: C1-1 1, C1-2 2, C1-3 3, C1-4 4, C1-5 5, C1-6 6, C1-7 7, C1-8 8
part F pins: C2-1 1, C2-2 2, C2-3 3, C2-4 4, C2-5 5, C2-6 6, C2-7 7, C2-8 8
part G pins: D1-1 1, D1-2 2, D1-3 3, D1-4 4, D1-5 5, D1-6 6, D1-7 7, D1-8 8
part H pins: D2-1 1, D2-2 2, D2-3 3, D2-4 4, D2-5 5, D2-6 6, D2-7 7, D2-8 8
part I pins: E1-1 1, E1-2 2, E1-3 3, E1-4 4, E1-5 5, E1-6 6, E1-7 7, E1-8 8
part J pins: E2-1 1, E2-2 2, E2-3 3, E2-4 4, E2-5 5, E2-6 6, E2-7 7, E2-8 8
part K pins: F1-1 1, F1-2 2, F1-3 3, F1-4 4, F1-5 5, F1-6 6, F1-7 7, F1-8 8
part L pins: F2-1 1, F2-2 2, F2-3 3, F2-4 4, F2-5 5, F2-6 6, F2-7 7, F2-8 8

## 44520-0003
designator X?, comment STACKED MODULAR JACK CATEGORY 5   Source: http://www.molex.com/pdm_docs/sd/445200006_sd.pdf
MPN: 44520-0003
footprint 44520-0003
part A pins: A1-1 1, A1-2 2, A1-3 3, A1-4 4, A1-5 5, A1-6 6, A1-7 7, A1-8 8
part B pins: A2-1 1, A2-2 2, A2-3 3, A2-4 4, A2-5 5, A2-6 6, A2-7 7, A2-8 8
part C pins: B1-1 1, B1-2 2, B1-3 3, B1-4 4, B1-5 5, B1-6 6, B1-7 7, B1-8 8
part D pins: B2-1 1, B2-2 2, B2-3 3, B2-4 4, B2-5 5, B2-6 6, B2-7 7, B2-8 8
part E pins: C1-1 1, C1-2 2, C1-3 3, C1-4 4, C1-5 5, C1-6 6, C1-7 7, C1-8 8
part F pins: C2-1 1, C2-2 2, C2-3 3, C2-4 4, C2-5 5, C2-6 6, C2-7 7, C2-8 8
part G pins: D1-1 1, D1-2 2, D1-3 3, D1-4 4, D1-5 5, D1-6 6, D1-7 7, D1-8 8
part H pins: D2-1 1, D2-2 2, D2-3 3, D2-4 4, D2-5 5, D2-6 6, D2-7 7, D2-8 8
part I pins: E1-1 1, E1-2 2, E1-3 3, E1-4 4, E1-5 5, E1-6 6, E1-7 7, E1-8 8
part J pins: E2-1 1, E2-2 2, E2-3 3, E2-4 4, E2-5 5, E2-6 6, E2-7 7, E2-8 8
part K pins: F1-1 1, F1-2 2, F1-3 3, F1-4 4, F1-5 5, F1-6 6, F1-7 7, F1-8 8
part L pins: F2-1 1, F2-2 2, F2-3 3, F2-4 4, F2-5 5, F2-6 6, F2-7 7, F2-8 8
part M pins: G1-1 1, G1-2 2, G1-3 3, G1-4 4, G1-5 5, G1-6 6, G1-7 7, G1-8 8
part N pins: G2-1 1, G2-2 2, G2-3 3, G2-4 4, G2-5 5, G2-6 6, G2-7 7, G2-8 8
part O pins: H1-1 1, H1-2 2, H1-3 3, H1-4 4, H1-5 5, H1-6 6, H1-7 7, H1-8 8
part P pins: H2-1 1, H2-2 2, H2-3 3, H2-4 4, H2-5 5, H2-6 6, H2-7 7, H2-8 8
